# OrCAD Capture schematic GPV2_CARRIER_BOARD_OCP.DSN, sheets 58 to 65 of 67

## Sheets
58 064 P1V8: size C
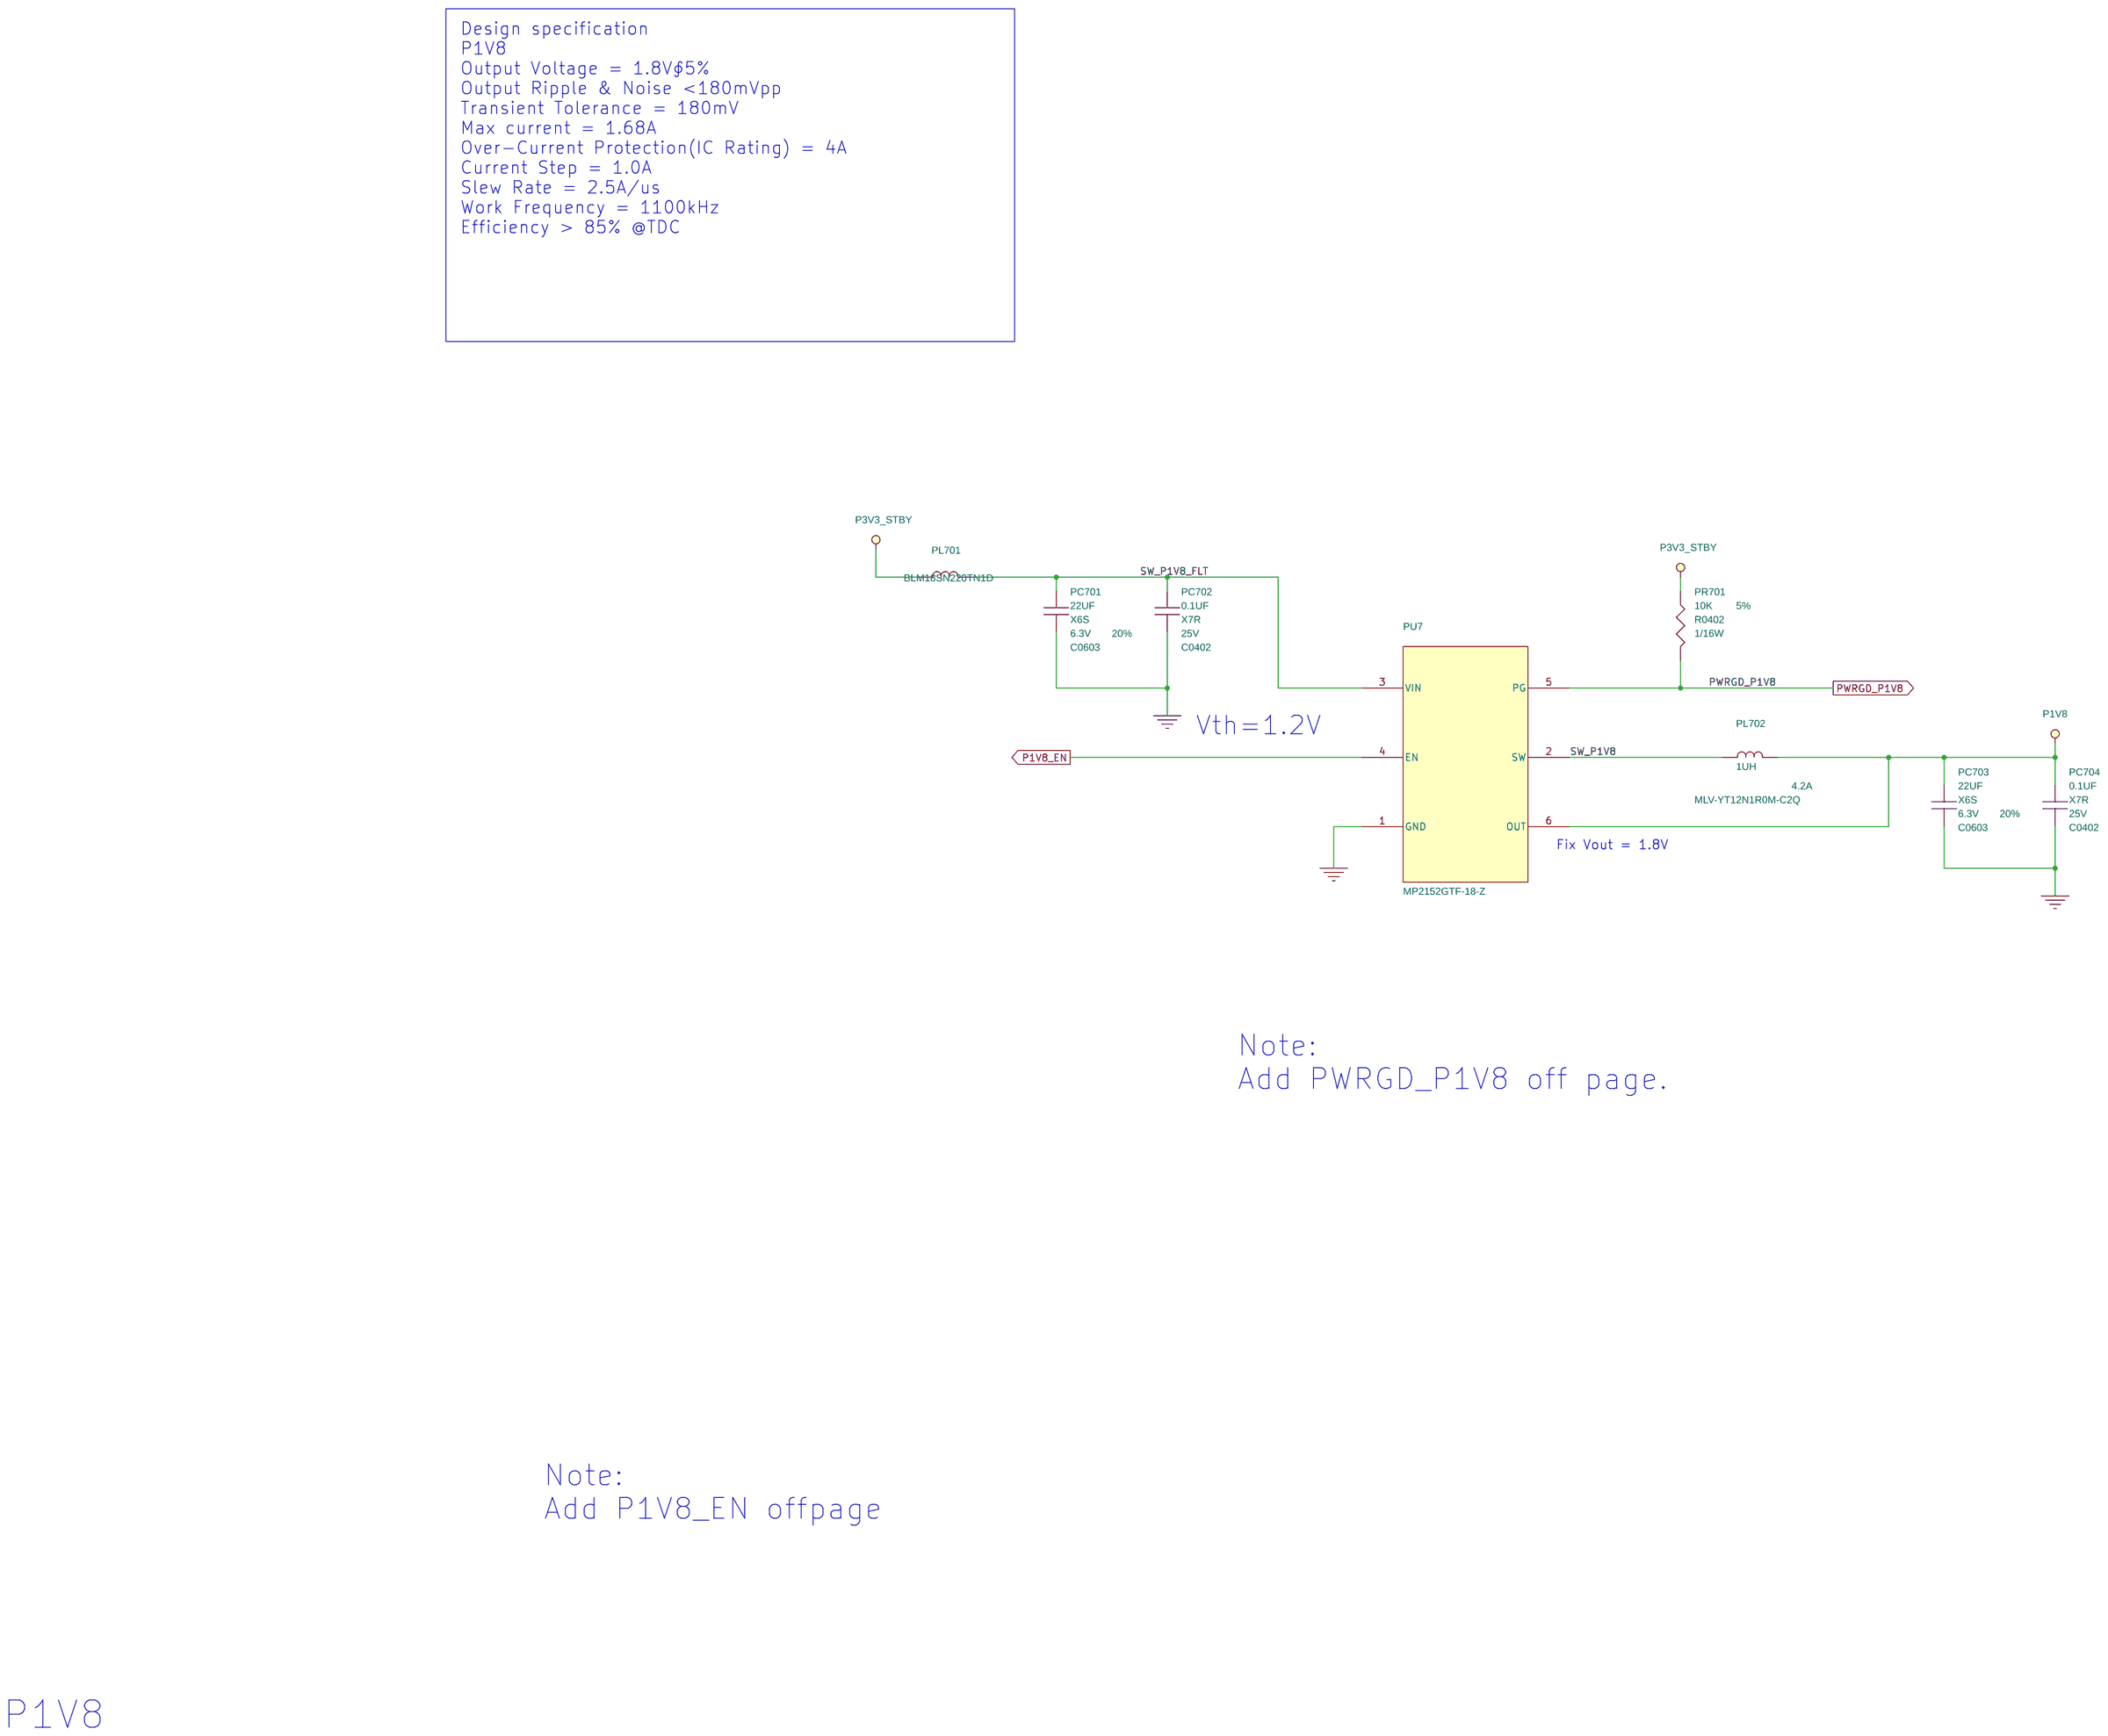
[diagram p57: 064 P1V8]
59 066 TDR: size C
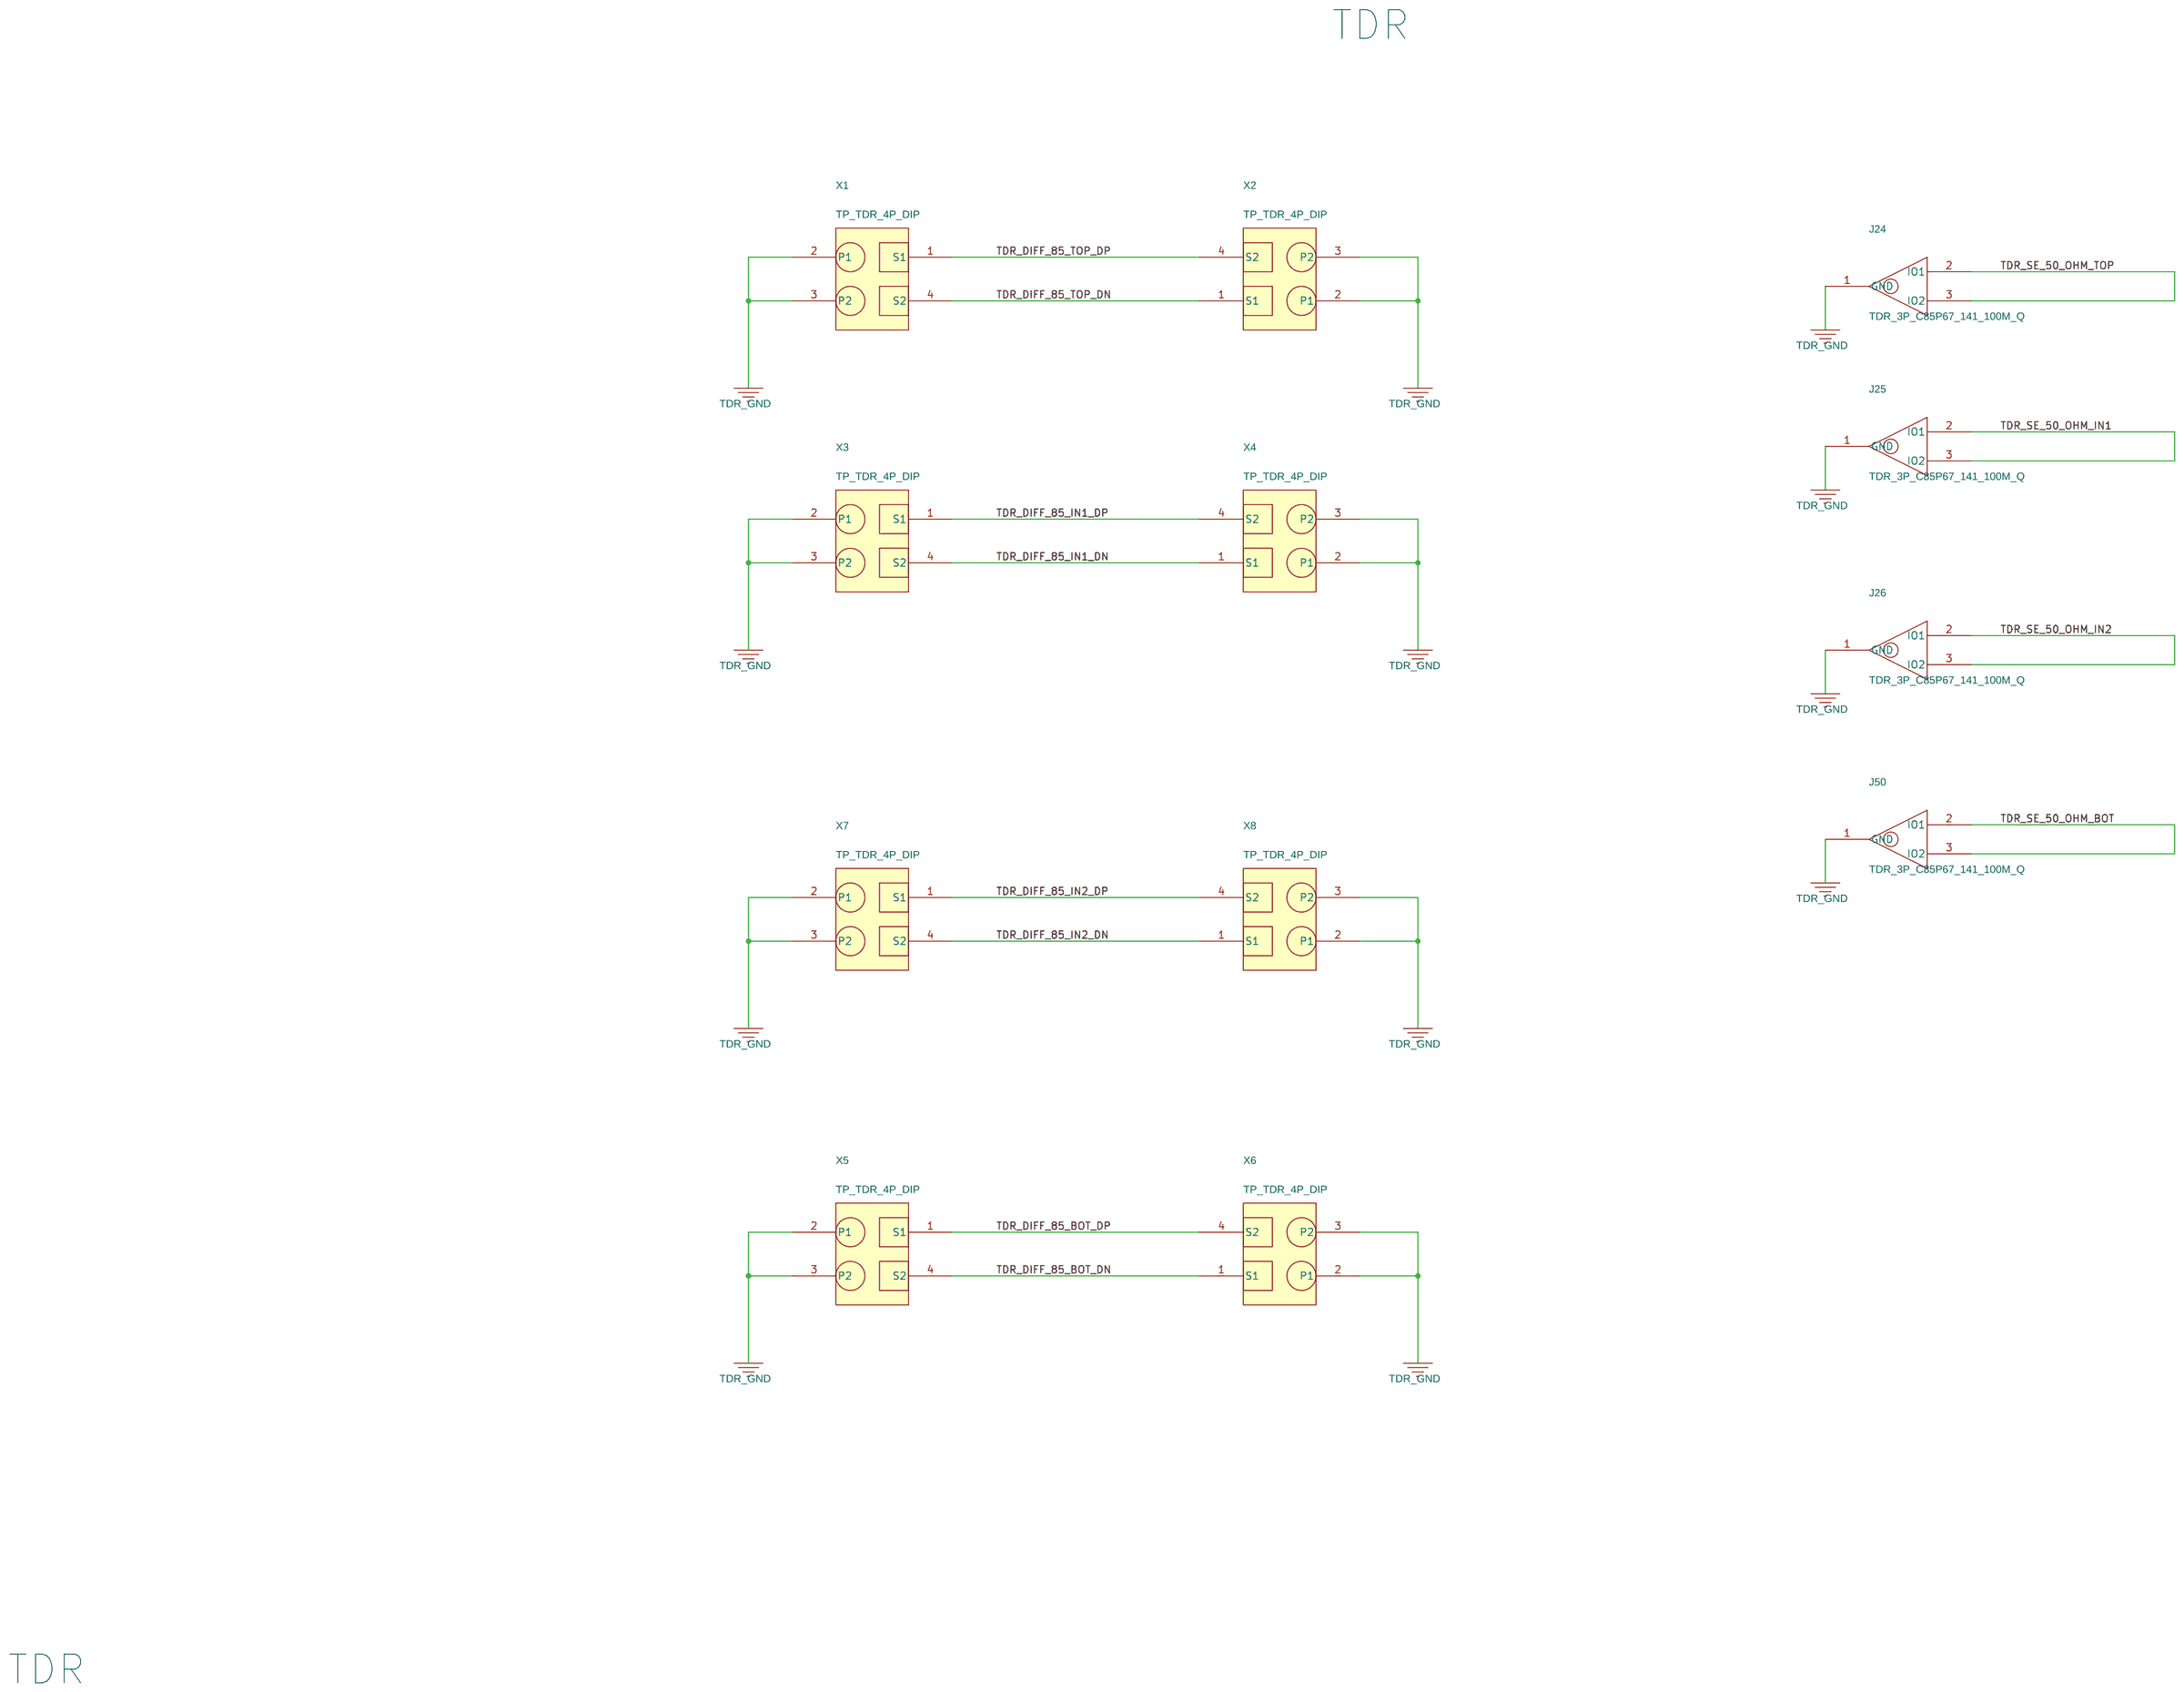
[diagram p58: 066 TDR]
60 067 DUMMY SYMBOL: size C
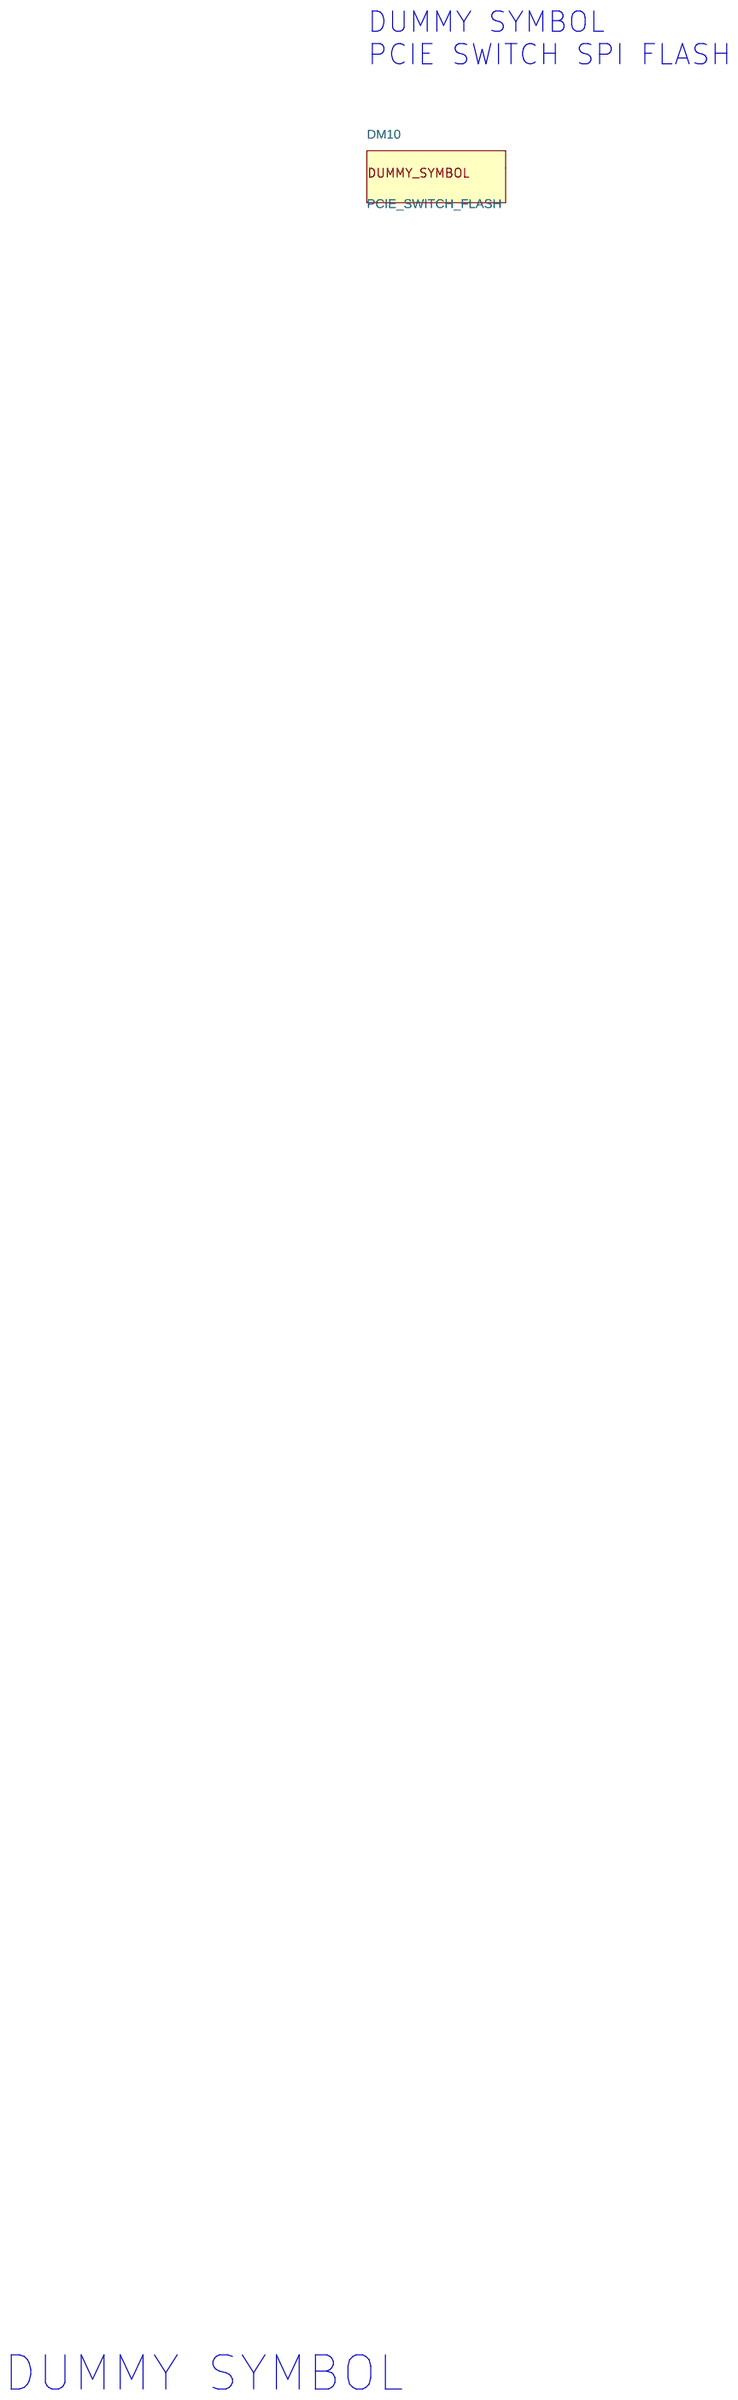
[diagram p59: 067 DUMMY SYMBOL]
61 041 INA230 / I2C MUX 7: size C
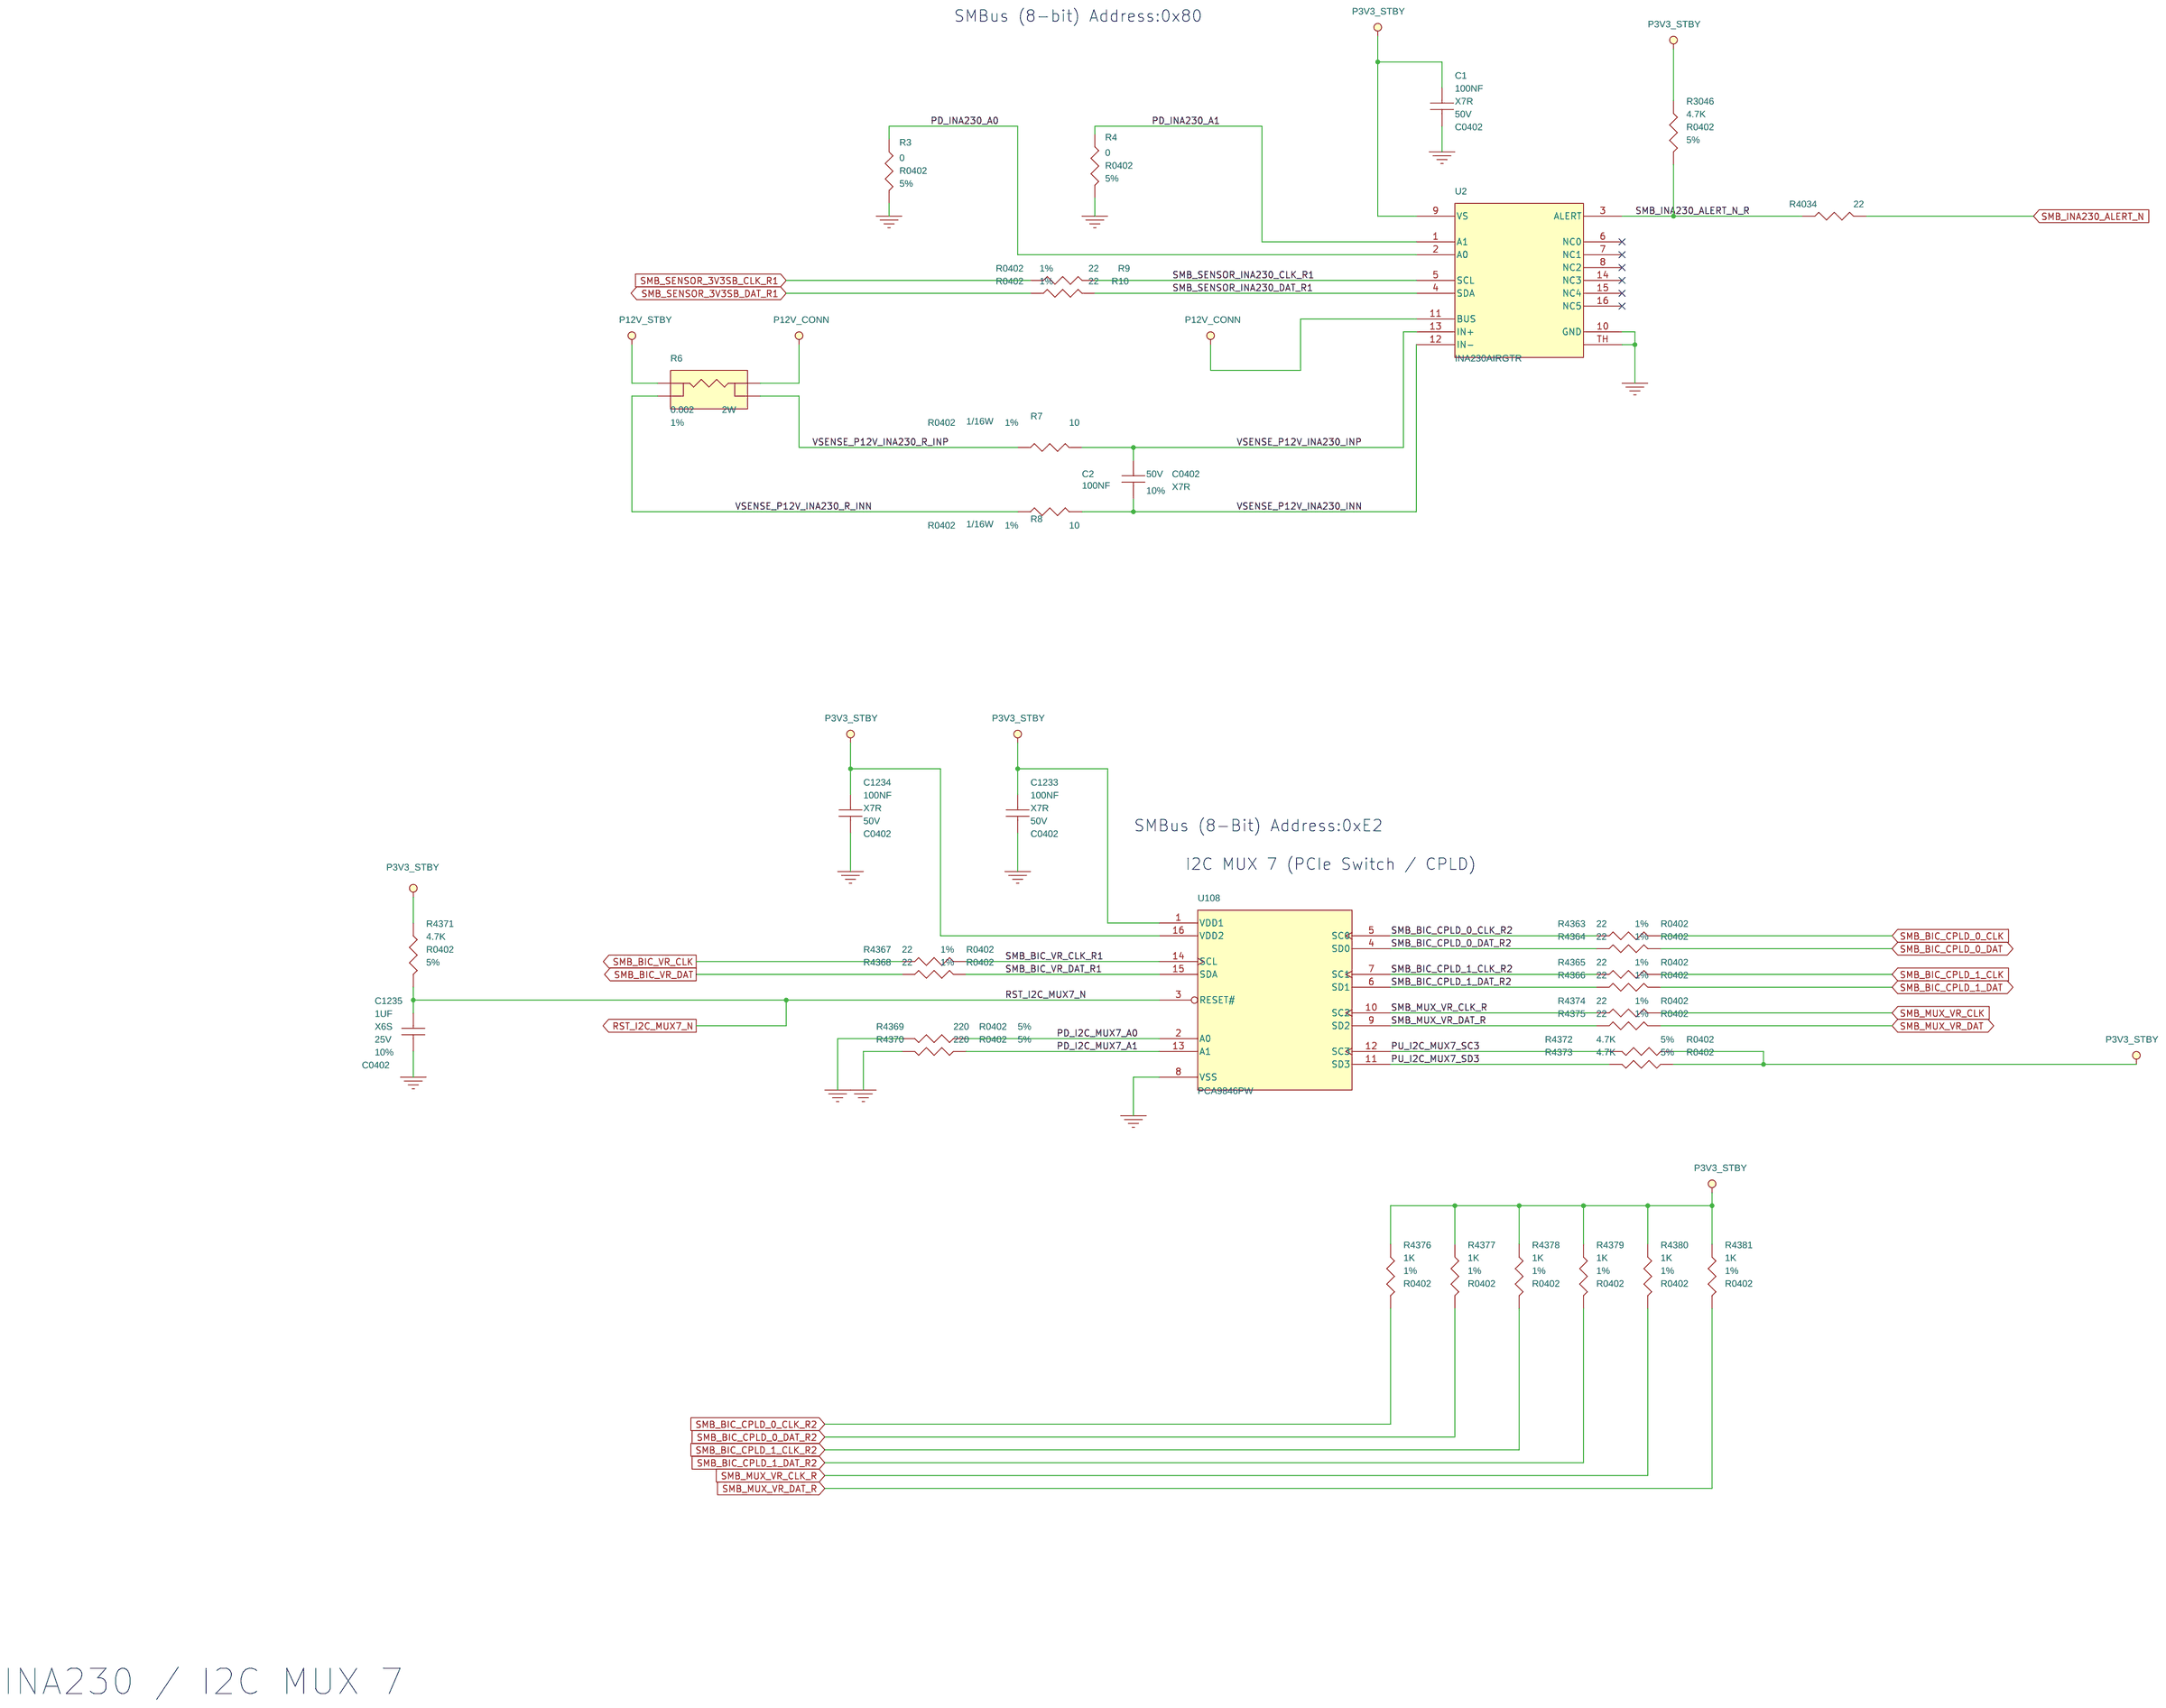
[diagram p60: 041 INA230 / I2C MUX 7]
62 022 SPI FLASH/EEPROM/JTAG: size C
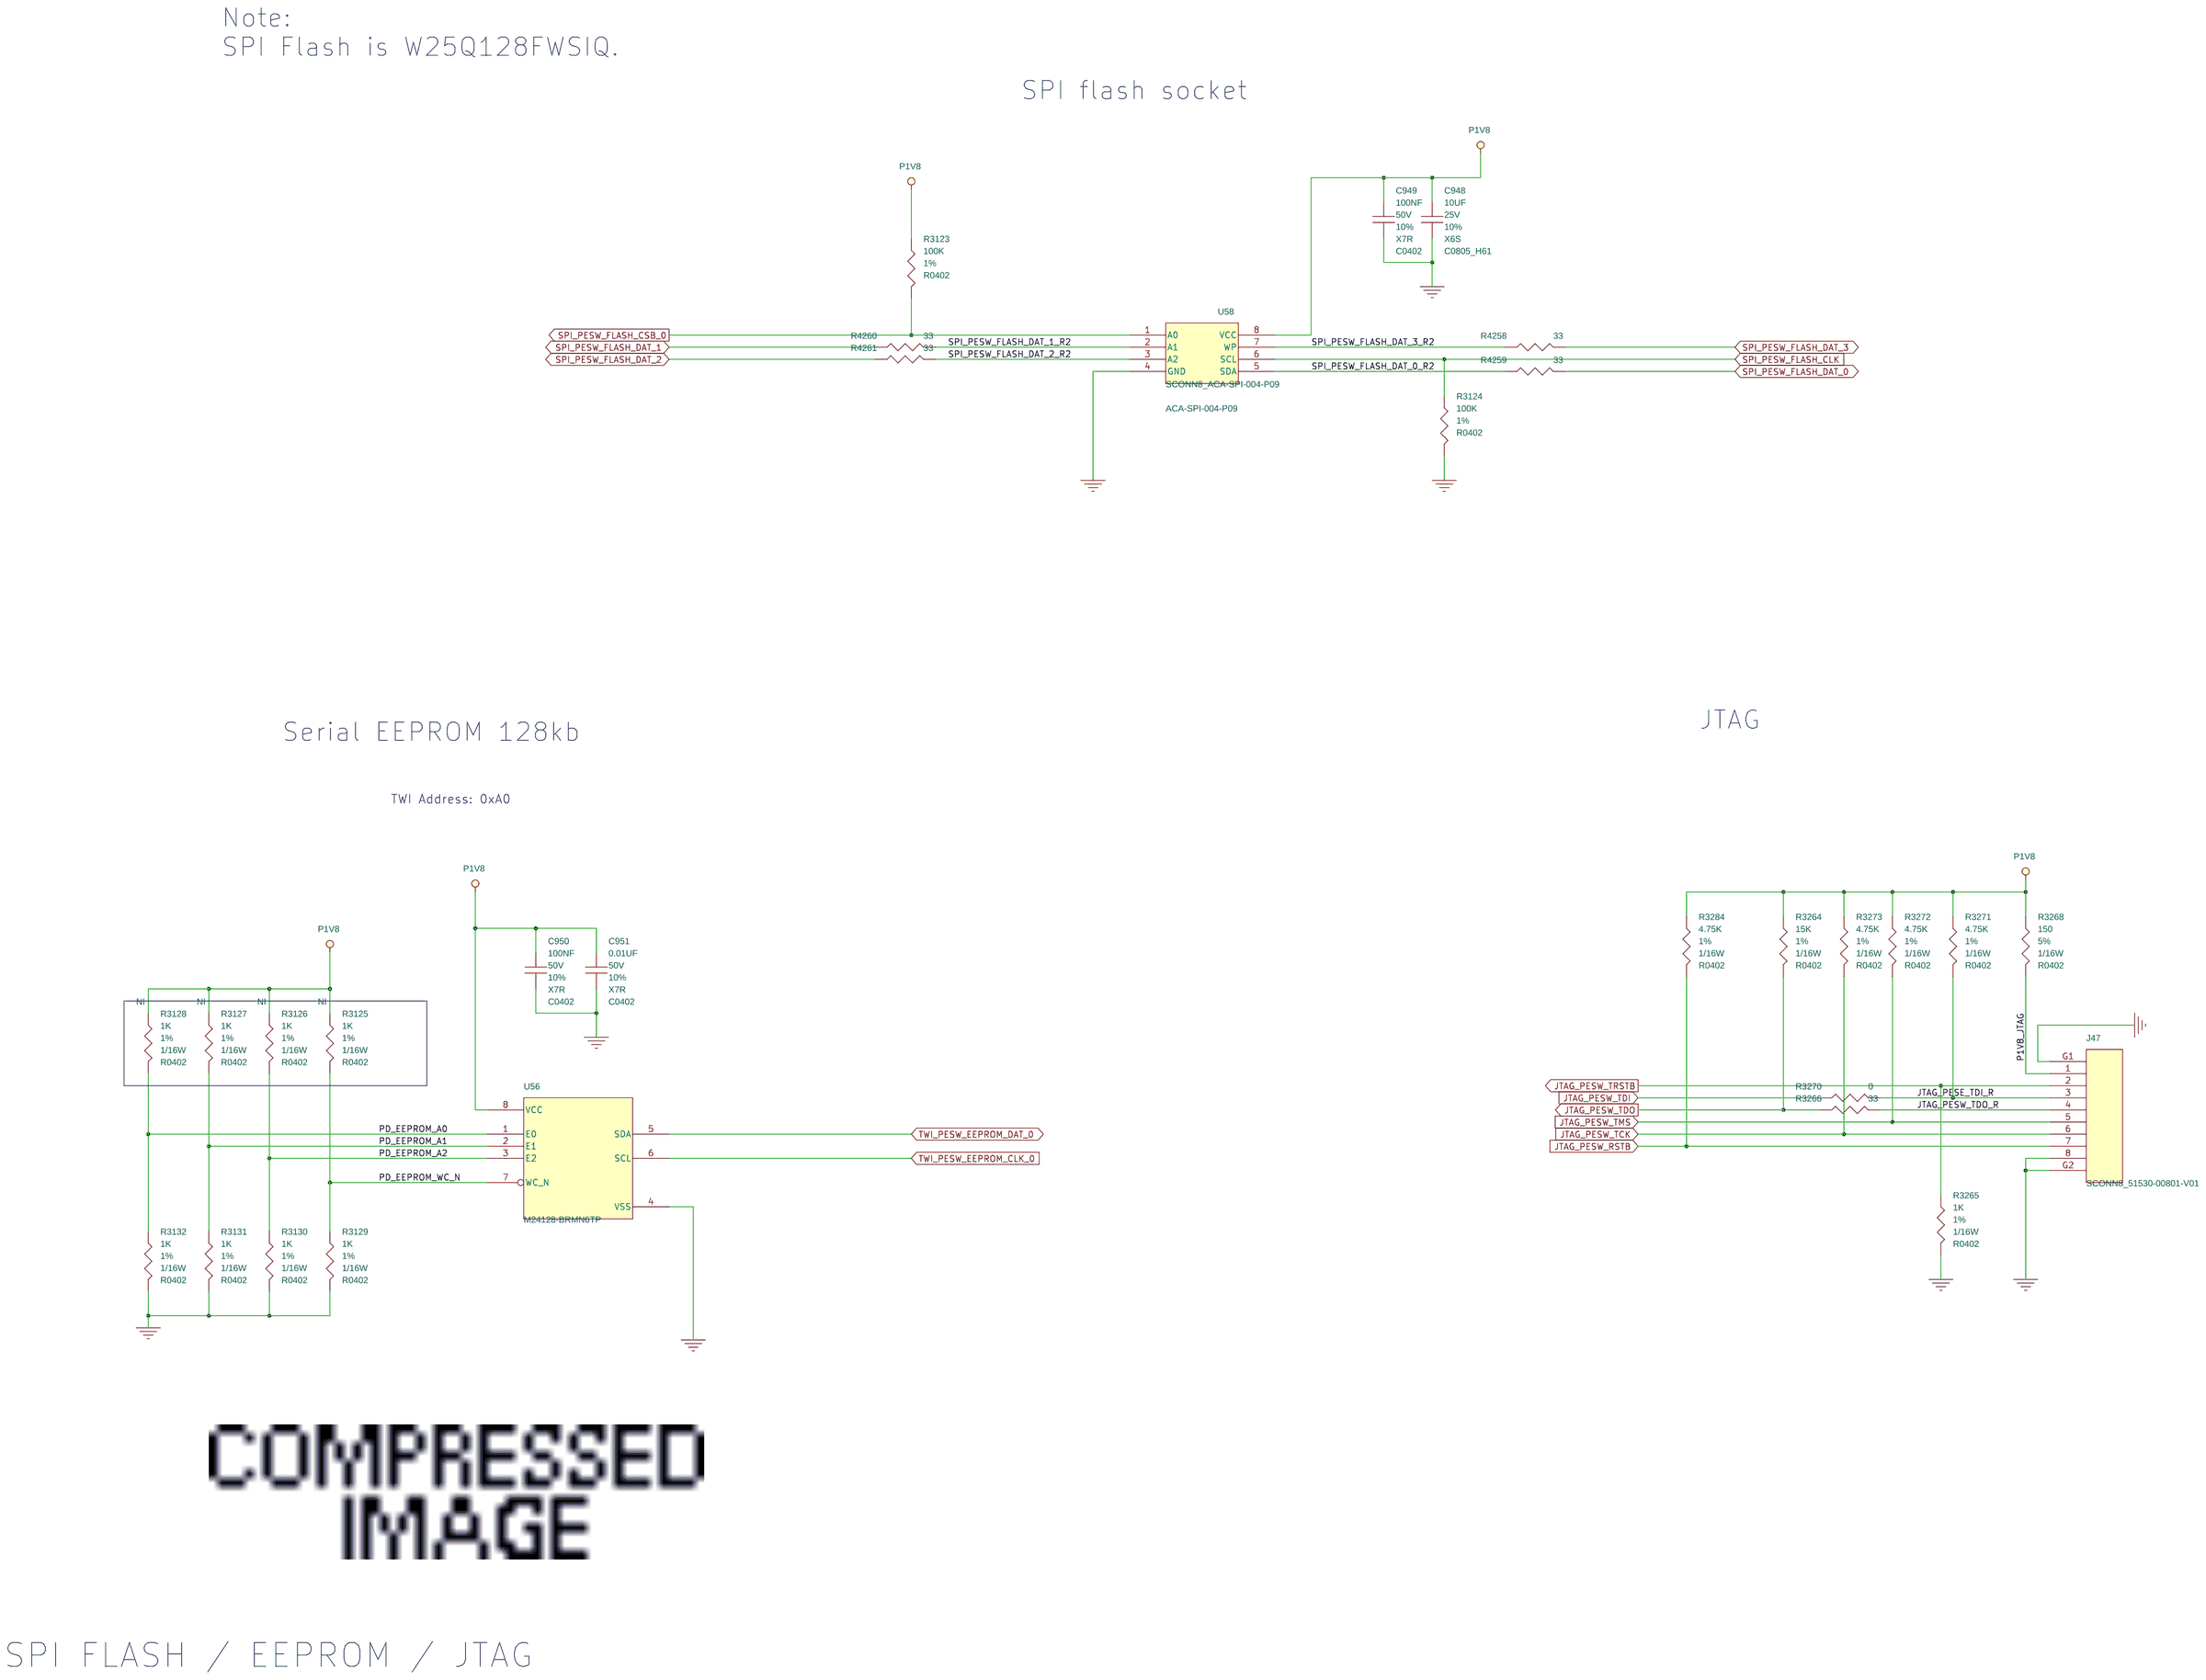
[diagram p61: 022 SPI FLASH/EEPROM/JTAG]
63 065 Mechanical/Delta-L: size C
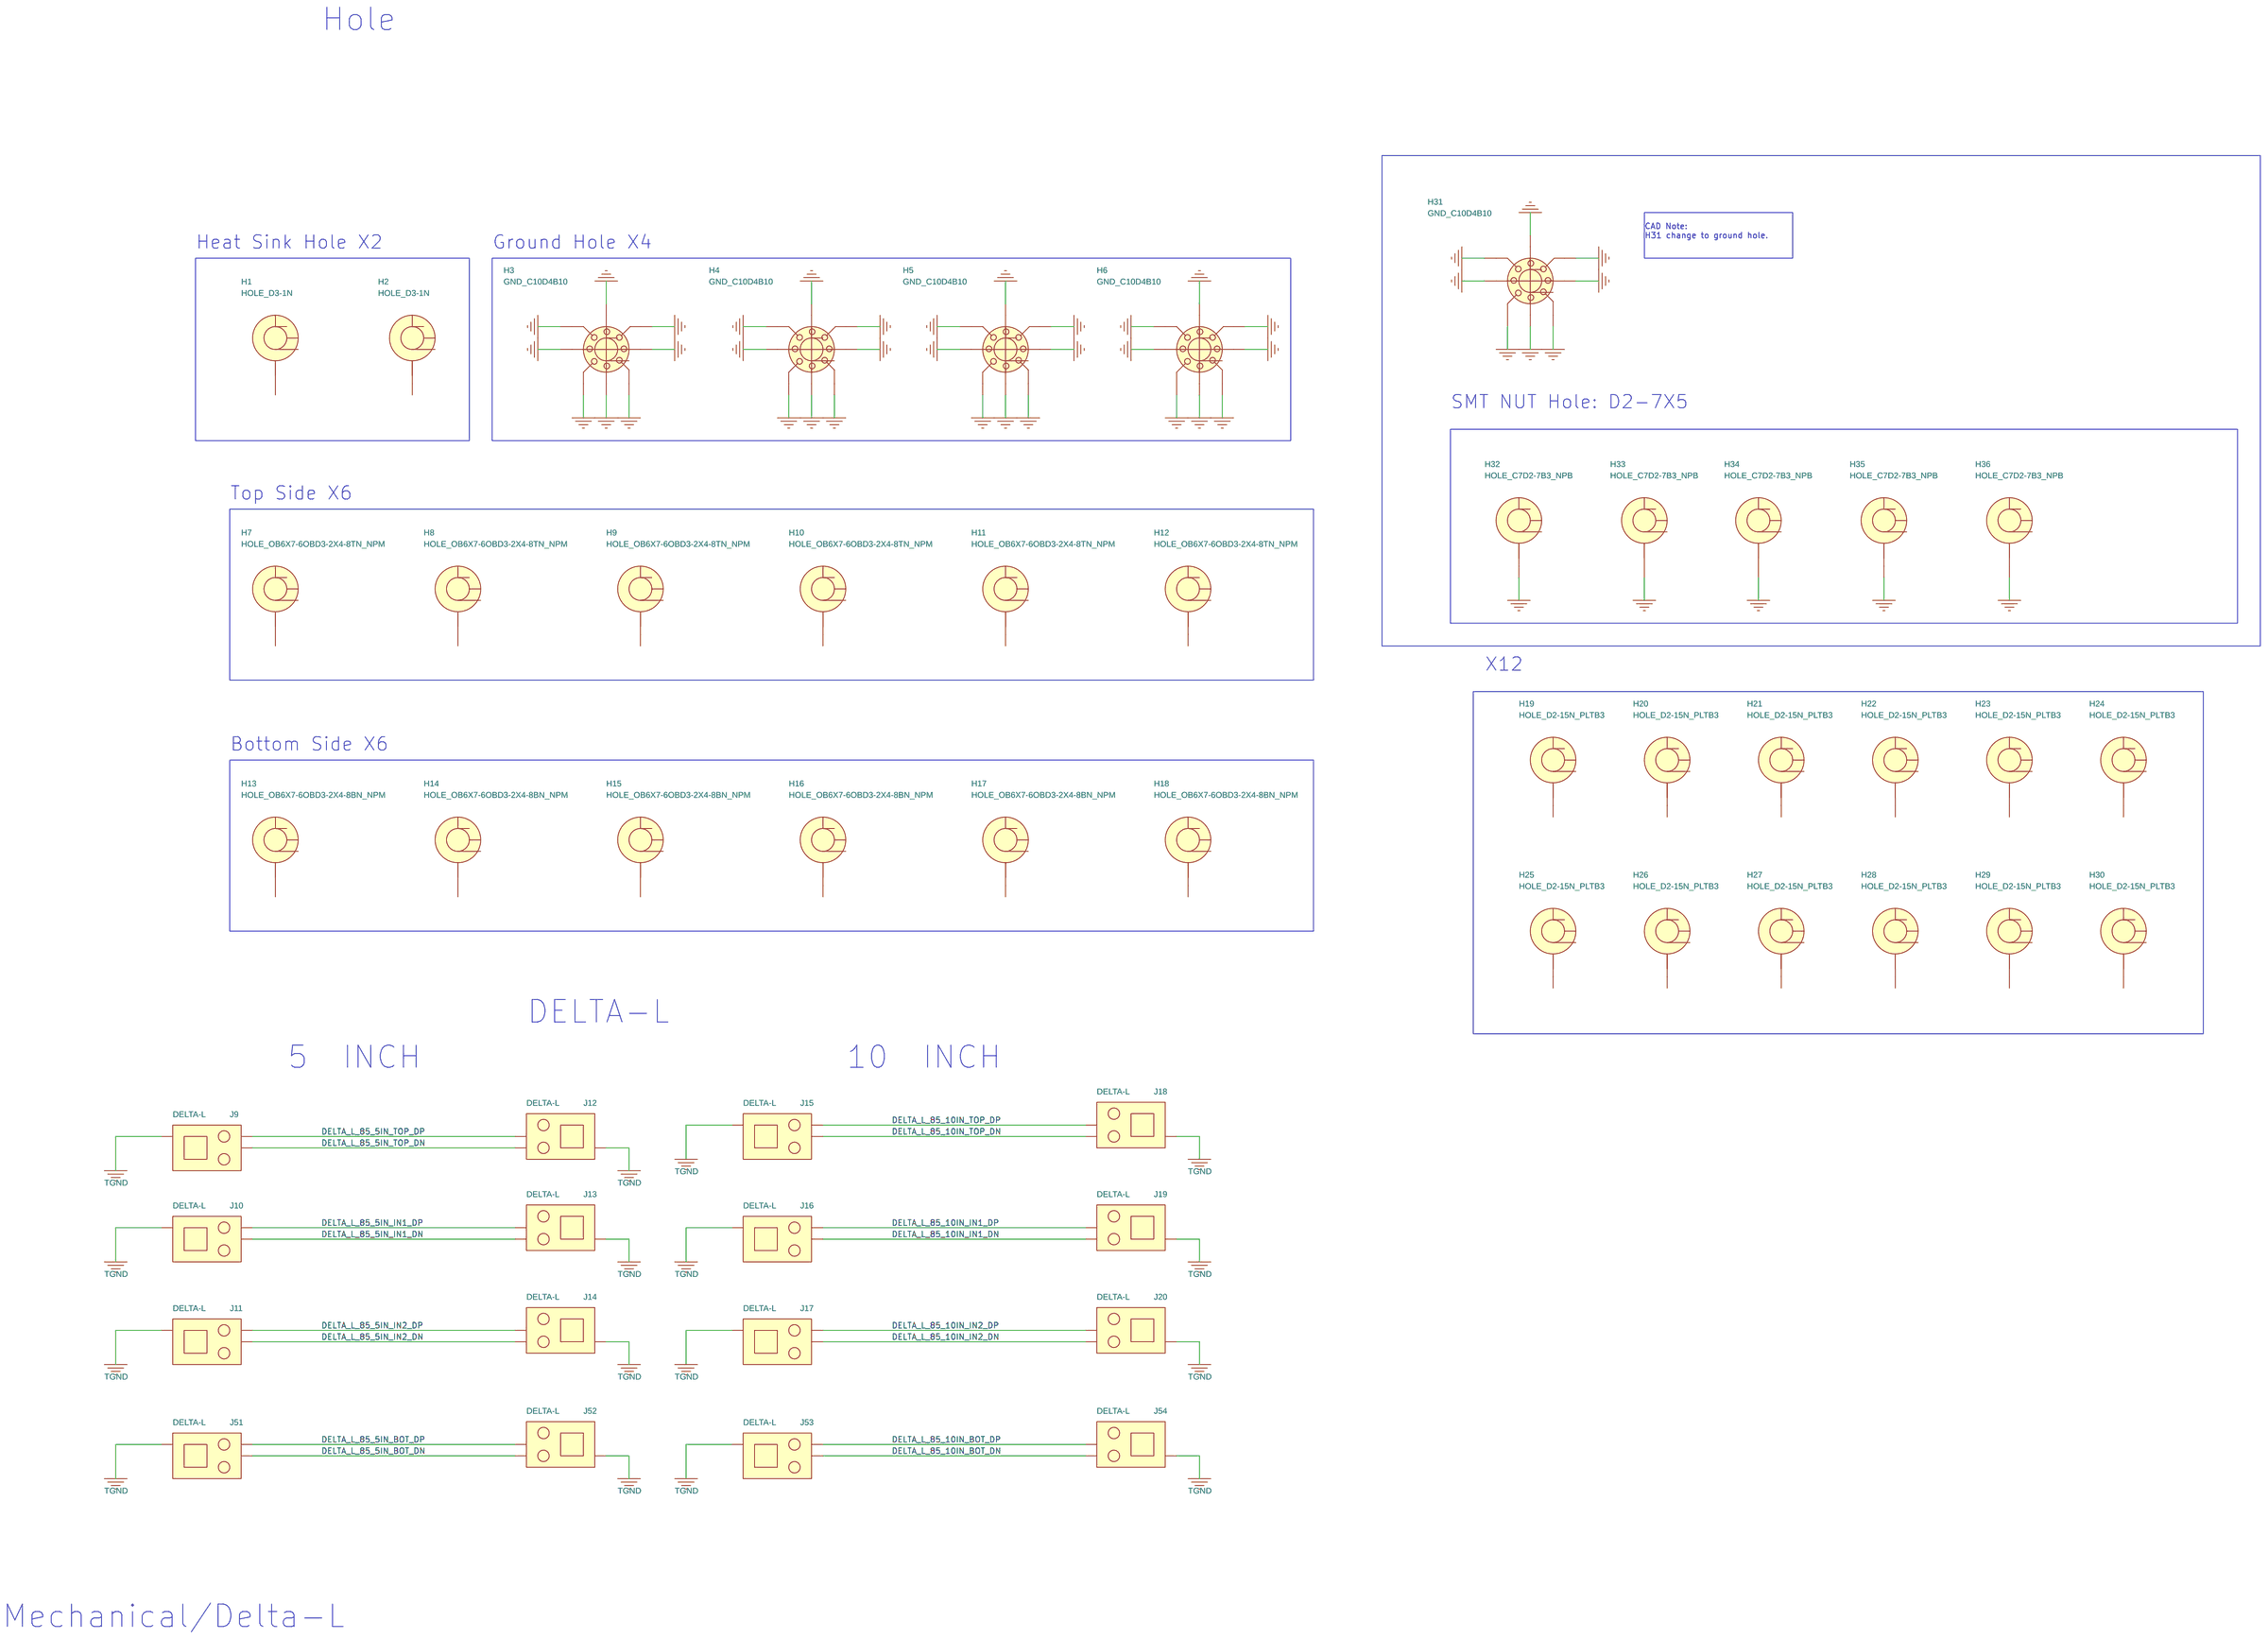
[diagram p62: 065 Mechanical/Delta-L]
64 020 PCIE SWITCH (PWR2/VSS2): size C
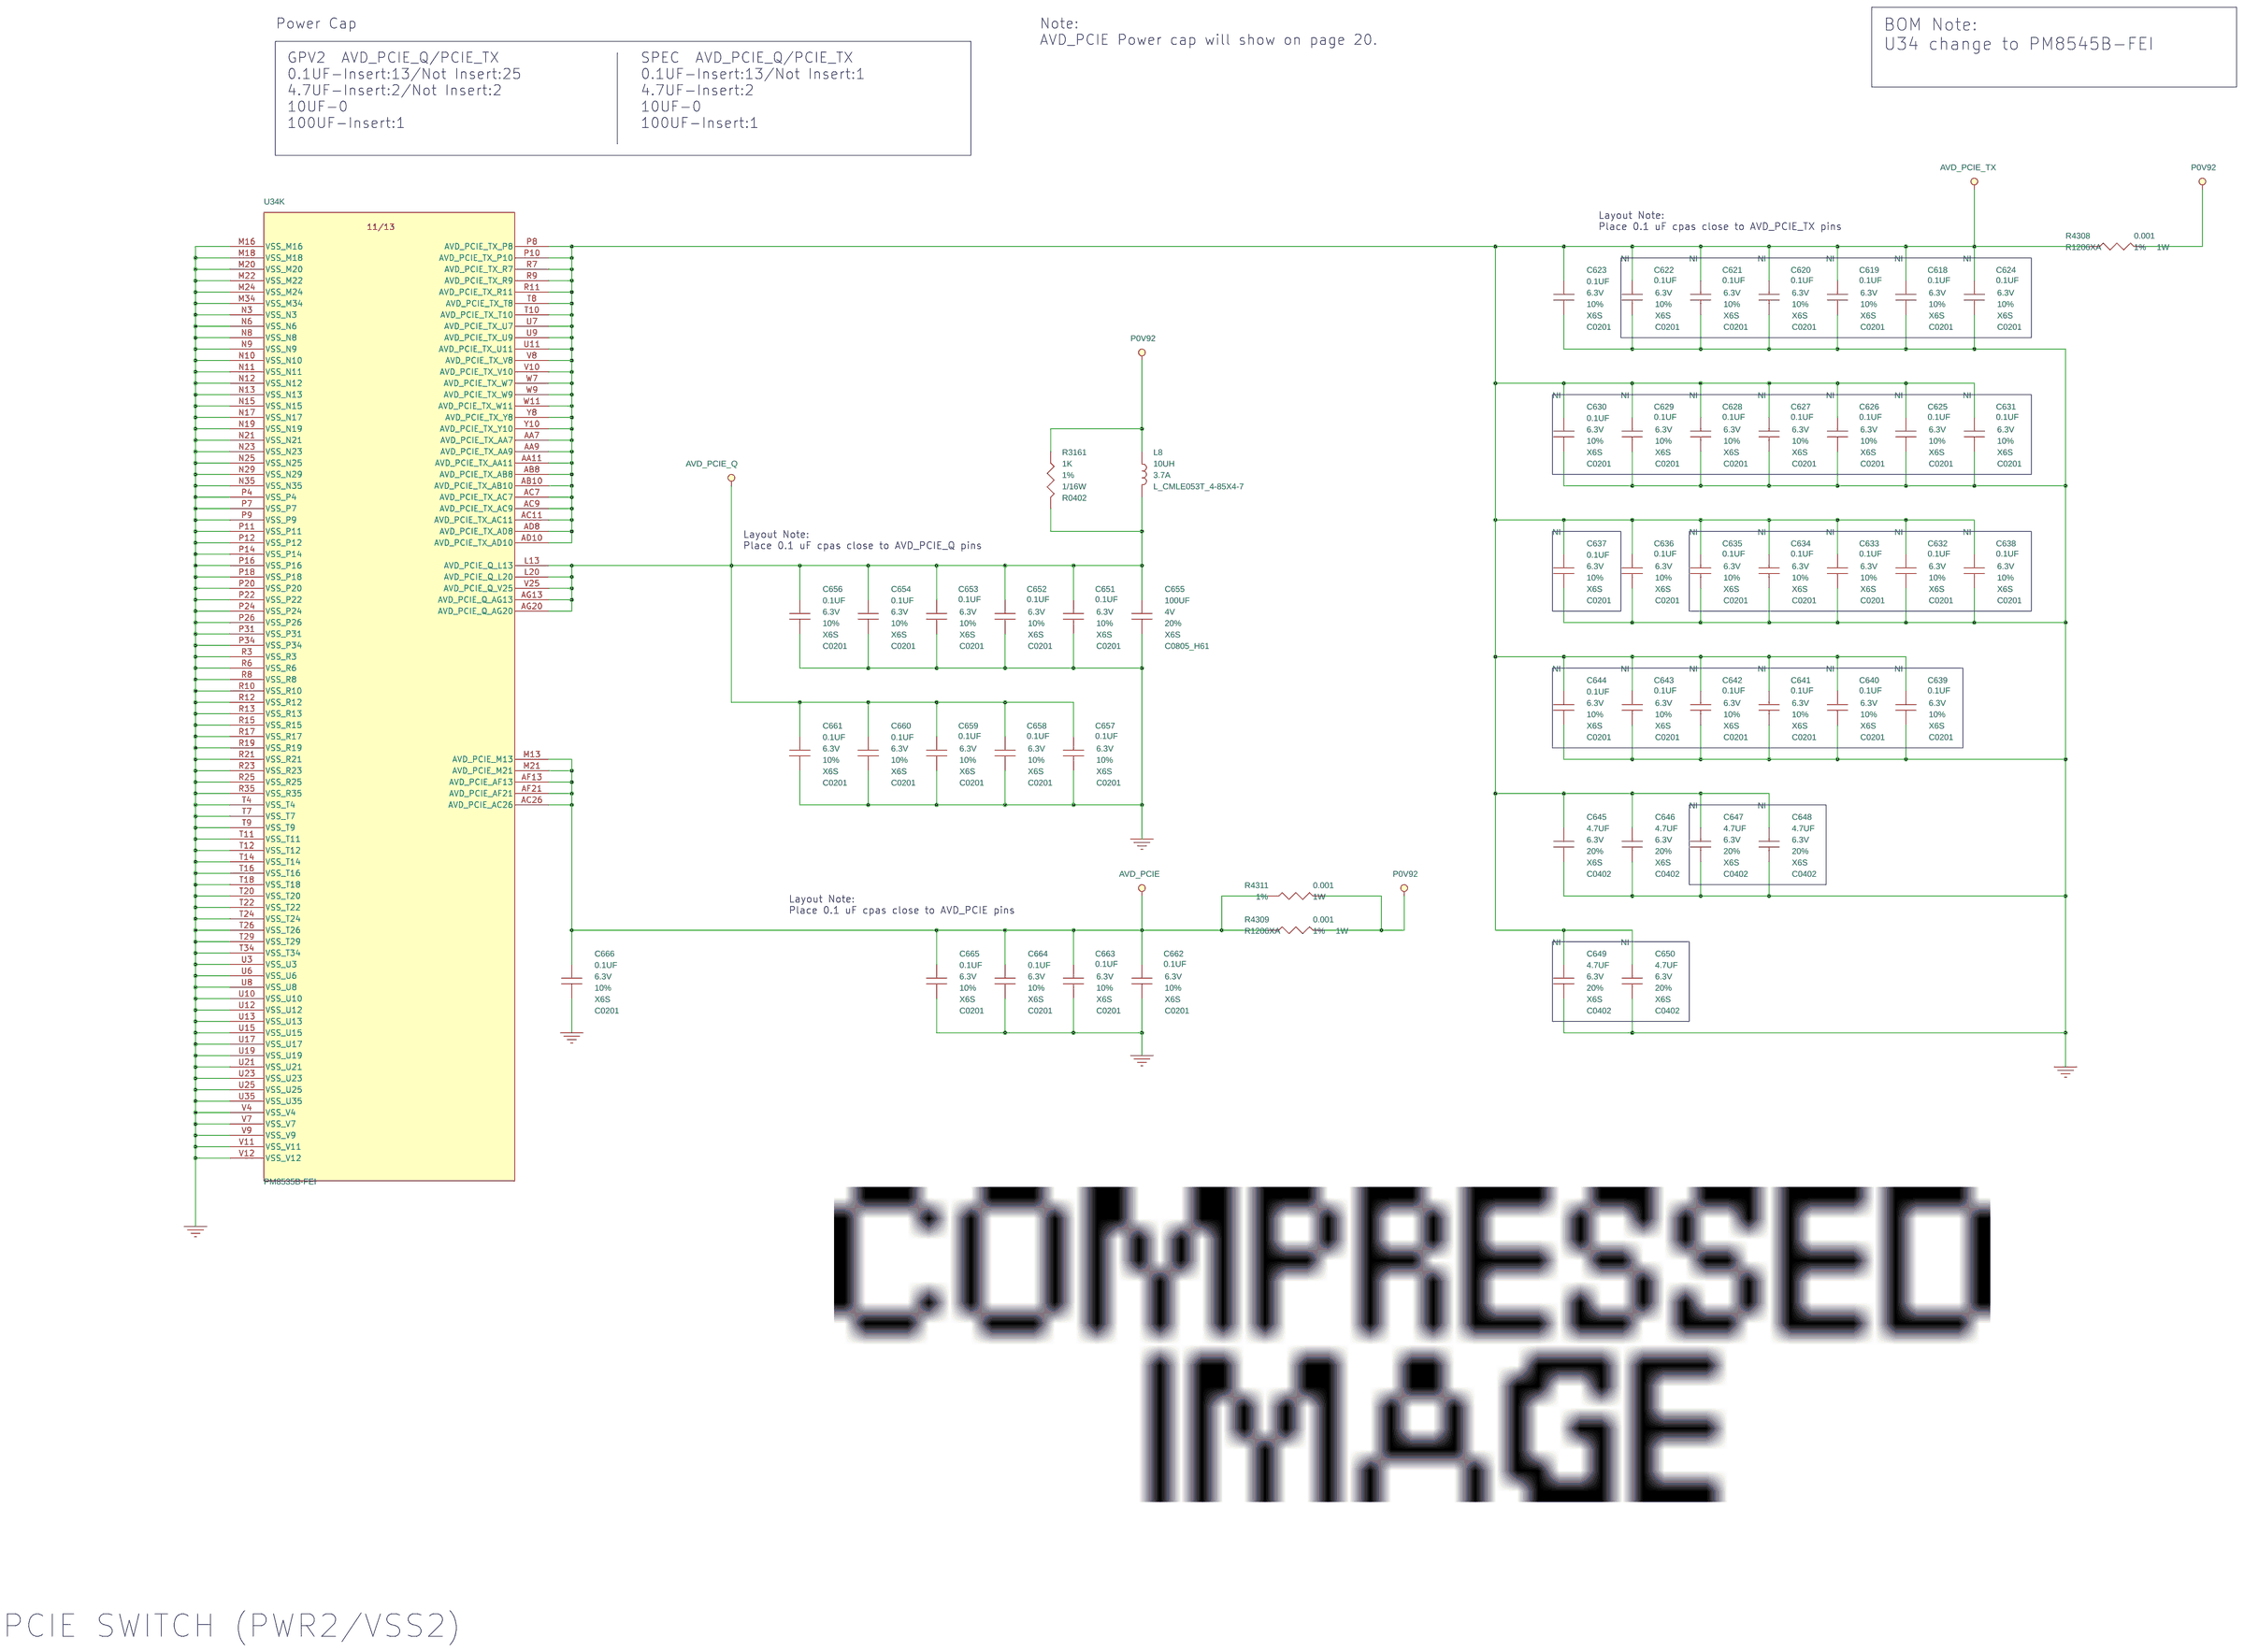
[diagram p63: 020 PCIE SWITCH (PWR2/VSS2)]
65 019 PCIE SWITCH (PWR1/VSS1): size C
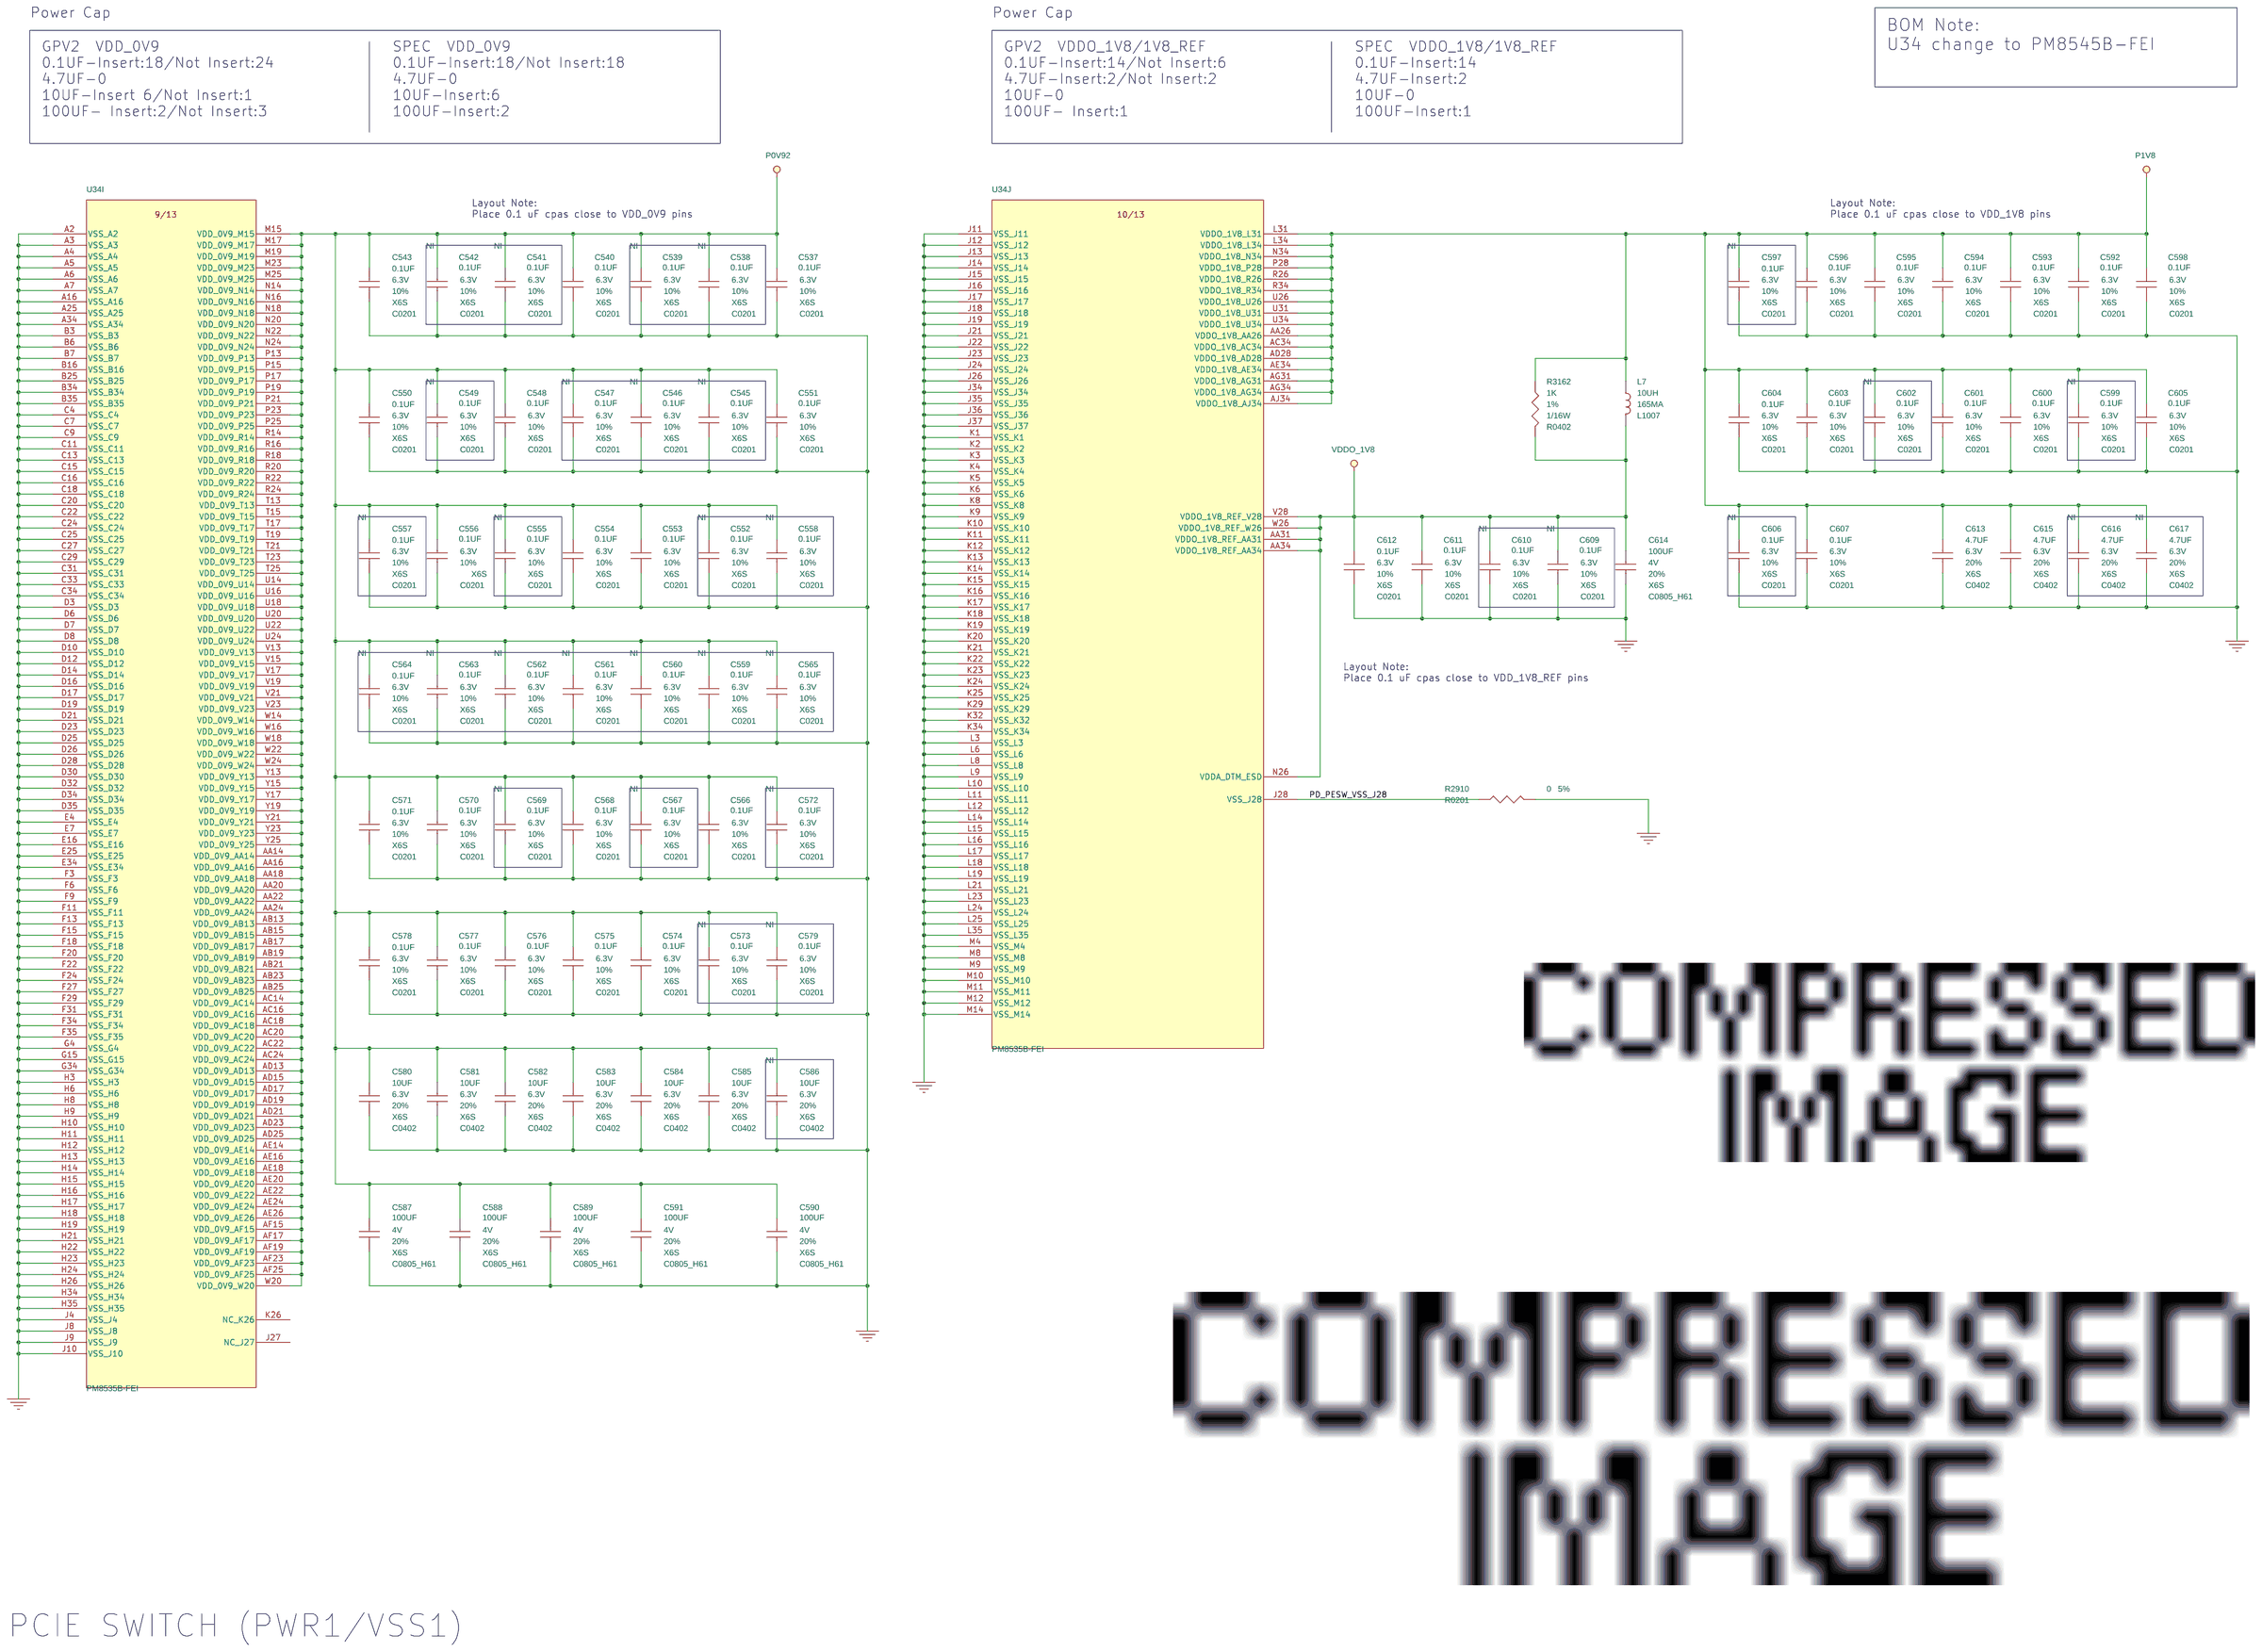
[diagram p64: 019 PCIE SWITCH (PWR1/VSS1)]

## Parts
sheet 017 PCIE SWITCH (CLOCKS/RESET)
U34  PM8535B-FEI  [BGA1311_1_37-5X37-5]  (sections A,B,C,D,E,F,G,H,I,J,K,L,M)
sheet 019 PCIE SWITCH (PWR1/VSS1)
C537  0.1UF  [C0201]
C538  0.1UF  [C0201]
C539  0.1UF  [C0201]
C540  0.1UF  [C0201]
C541  0.1UF  [C0201]
C542  0.1UF  [C0201]
C543  0.1UF  [C0201]
C545  0.1UF  [C0201]
C546  0.1UF  [C0201]
C547  0.1UF  [C0201]
C548  0.1UF  [C0201]
C549  0.1UF  [C0201]
C550  0.1UF  [C0201]
C551  0.1UF  [C0201]
C552  0.1UF  [C0201]
C553  0.1UF  [C0201]
C554  0.1UF  [C0201]
C555  0.1UF  [C0201]
C556  0.1UF  [C0201]
C557  0.1UF  [C0201]
C558  0.1UF  [C0201]
C559  0.1UF  [C0201]
C560  0.1UF  [C0201]
C561  0.1UF  [C0201]
C562  0.1UF  [C0201]
C563  0.1UF  [C0201]
C564  0.1UF  [C0201]
C565  0.1UF  [C0201]
C566  0.1UF  [C0201]
C567  0.1UF  [C0201]
C568  0.1UF  [C0201]
C569  0.1UF  [C0201]
C570  0.1UF  [C0201]
C571  0.1UF  [C0201]
C572  0.1UF  [C0201]
C573  0.1UF  [C0201]
C574  0.1UF  [C0201]
C575  0.1UF  [C0201]
C576  0.1UF  [C0201]
C577  0.1UF  [C0201]
C578  0.1UF  [C0201]
C579  0.1UF  [C0201]
C580  10UF  [C0402]
C581  10UF  [C0402]
C582  10UF  [C0402]
C583  10UF  [C0402]
C584  10UF  [C0402]
C585  10UF  [C0402]
C586  10UF  [C0402]
C587  100UF  [C0805_H61]
C588  100UF  [C0805_H61]
C589  100UF  [C0805_H61]
C590  100UF  [C0805_H61]
C591  100UF  [C0805_H61]
C592  0.1UF  [C0201]
C593  0.1UF  [C0201]
C594  0.1UF  [C0201]
C595  0.1UF  [C0201]
C596  0.1UF  [C0201]
C597  0.1UF  [C0201]
C598  0.1UF  [C0201]
C599  0.1UF  [C0201]
C600  0.1UF  [C0201]
C601  0.1UF  [C0201]
C602  0.1UF  [C0201]
C603  0.1UF  [C0201]
C604  0.1UF  [C0201]
C605  0.1UF  [C0201]
C606  0.1UF  [C0201]
C607  0.1UF  [C0201]
C609  0.1UF  [C0201]
C610  0.1UF  [C0201]
C611  0.1UF  [C0201]
C612  0.1UF  [C0201]
C613  4.7UF  [C0402]
C614  100UF  [C0805_H61]
C615  4.7UF  [C0402]
C616  4.7UF  [C0402]
C617  4.7UF  [C0402]
L7  10UH  [L1007]
R2910  0  [R0201]
R3162  1K  [R0402]
sheet 020 PCIE SWITCH (PWR2/VSS2)
C618  0.1UF  [C0201]
C619  0.1UF  [C0201]
C620  0.1UF  [C0201]
C621  0.1UF  [C0201]
C622  0.1UF  [C0201]
C623  0.1UF  [C0201]
C624  0.1UF  [C0201]
C625  0.1UF  [C0201]
C626  0.1UF  [C0201]
C627  0.1UF  [C0201]
C628  0.1UF  [C0201]
C629  0.1UF  [C0201]
C630  0.1UF  [C0201]
C631  0.1UF  [C0201]
C632  0.1UF  [C0201]
C633  0.1UF  [C0201]
C634  0.1UF  [C0201]
C635  0.1UF  [C0201]
C636  0.1UF  [C0201]
C637  0.1UF  [C0201]
C638  0.1UF  [C0201]
C639  0.1UF  [C0201]
C640  0.1UF  [C0201]
C641  0.1UF  [C0201]
C642  0.1UF  [C0201]
C643  0.1UF  [C0201]
C644  0.1UF  [C0201]
C645  4.7UF  [C0402]
C646  4.7UF  [C0402]
C647  4.7UF  [C0402]
C648  4.7UF  [C0402]
C649  4.7UF  [C0402]
C650  4.7UF  [C0402]
C651  0.1UF  [C0201]
C652  0.1UF  [C0201]
C653  0.1UF  [C0201]
C654  0.1UF  [C0201]
C655  100UF  [C0805_H61]
C656  0.1UF  [C0201]
C657  0.1UF  [C0201]
C658  0.1UF  [C0201]
C659  0.1UF  [C0201]
C660  0.1UF  [C0201]
C661  0.1UF  [C0201]
C662  0.1UF  [C0201]
C663  0.1UF  [C0201]
C664  0.1UF  [C0201]
C665  0.1UF  [C0201]
C666  0.1UF  [C0201]
L8  10UH  [L_CMLE053T_4-85X4-7]
R3161  1K  [R0402]
R4308  0.001  [R1206XA]
R4309  0.001  [R1206XA]
R4311  0.001  [R1206XA]
sheet 022 SPI FLASH/EEPROM/JTAG
C948  10UF  [C0805_H61]
C949  100NF  [C0402]
C950  100NF  [C0402]
C951  0.01UF  [C0402]
J47  SCONN8_51530-00801-V01  [CON_8S1H2S_P0-5XC]
R3123  100K  [R0402]
R3124  100K  [R0402]
R3125  1K  [R0402]
R3126  1K  [R0402]
R3127  1K  [R0402]
R3128  1K  [R0402]
R3129  1K  [R0402]
R3130  1K  [R0402]
R3131  1K  [R0402]
R3132  1K  [R0402]
R3264  15K  [R0402]
R3265  1K  [R0402]
R3266  33  [R0402]
R3268  150  [R0402]
R3270  0  [R0402]
R3271  4.75K  [R0402]
R3272  4.75K  [R0402]
R3273  4.75K  [R0402]
R3284  4.75K  [R0402]
R4258  33  [R0402]
R4259  33  [R0402]
R4260  33  [R0402]
R4261  33  [R0402]
U56  M24128-BRMN6TP  [SO8_1-27_4-9X3-9XA]
U58  SCONN8_ACA-SPI-004-P09  [SOCKET8SXD]
sheet 041 INA230 / I2C MUX 7
C1  100NF  [C0402]
C2  100NF  [C0402]
C1233  100NF  [C0402]
C1234  100NF  [C0402]
C1235  1UF  [C0402]
R3  0  [R0402]
R4  0  [R0402]
R6  0.002  [R2512_4PXF]
R7  10  [R0402]
R8  10  [R0402]
R9  22  [R0402]
R10  22  [R0402]
R3046  4.7K  [R0402]
R4034  22  [R0402]
R4363  22  [R0402]
R4364  22  [R0402]
R4365  22  [R0402]
R4366  22  [R0402]
R4367  22  [R0402]
R4368  22  [R0402]
R4369  220  [R0402]
R4370  220  [R0402]
R4371  4.7K  [R0402]
R4372  4.7K  [R0402]
R4373  4.7K  [R0402]
R4374  22  [R0402]
R4375  22  [R0402]
R4376  1K  [R0402]
R4377  1K  [R0402]
R4378  1K  [R0402]
R4379  1K  [R0402]
R4380  1K  [R0402]
R4381  1K  [R0402]
U2  INA230AIRGTR  [QFN16_THXI]
U108  PCA9846PW  [TSSOP16XD]
sheet 064 P1V8
PC701  22UF  [C0603]
PC702  0.1UF  [C0402]
PC703  22UF  [C0603]
PC704  0.1UF  [C0402]
PL701  BLM18SN220TN1D  [L0603]
PL702  1UH  [L_MLV-YT12N_2-5X2]
PR701  10K  [R0402]
PU7  MP2152GTF-18-Z  [SOT563-6_0-5_1-6X1-2XB]
sheet 065 Mechanical/Delta-L
H1  HOLE_D3-1N  [HOLE_D3-1N]
H2  HOLE_D3-1N  [HOLE_D3-1N]
H3  GNDHOLE_8PIN  [GND_C10D4B10]
H4  GNDHOLE_8PIN  [GND_C10D4B10]
H5  GNDHOLE_8PIN  [GND_C10D4B10]
H6  GNDHOLE_8PIN  [GND_C10D4B10]
H7  HOLE_OB6X7-6OBD3-2X4-8TN_NPM  [HOLE_OB6X7-6OBD3-2X4-8TN_NPM]
H8  HOLE_OB6X7-6OBD3-2X4-8TN_NPM  [HOLE_OB6X7-6OBD3-2X4-8TN_NPM]
H9  HOLE_OB6X7-6OBD3-2X4-8TN_NPM  [HOLE_OB6X7-6OBD3-2X4-8TN_NPM]
H10  HOLE_OB6X7-6OBD3-2X4-8TN_NPM  [HOLE_OB6X7-6OBD3-2X4-8TN_NPM]
H11  HOLE_OB6X7-6OBD3-2X4-8TN_NPM  [HOLE_OB6X7-6OBD3-2X4-8TN_NPM]
H12  HOLE_OB6X7-6OBD3-2X4-8TN_NPM  [HOLE_OB6X7-6OBD3-2X4-8TN_NPM]
H13  HOLE_OB6X7-6OBD3-2X4-8BN_NPM  [HOLE_OB6X7-6OBD3-2X4-8BN_NPM]
H14  HOLE_OB6X7-6OBD3-2X4-8BN_NPM  [HOLE_OB6X7-6OBD3-2X4-8BN_NPM]
H15  HOLE_OB6X7-6OBD3-2X4-8BN_NPM  [HOLE_OB6X7-6OBD3-2X4-8BN_NPM]
H16  HOLE_OB6X7-6OBD3-2X4-8BN_NPM  [HOLE_OB6X7-6OBD3-2X4-8BN_NPM]
H17  HOLE_OB6X7-6OBD3-2X4-8BN_NPM  [HOLE_OB6X7-6OBD3-2X4-8BN_NPM]
H18  HOLE_OB6X7-6OBD3-2X4-8BN_NPM  [HOLE_OB6X7-6OBD3-2X4-8BN_NPM]
H19  HOLE_D2-15N_PLTB3  [HOLE_D2-15N_PLTB3]
H20  HOLE_D2-15N_PLTB3  [HOLE_D2-15N_PLTB3]
H21  HOLE_D2-15N_PLTB3  [HOLE_D2-15N_PLTB3]
H22  HOLE_D2-15N_PLTB3  [HOLE_D2-15N_PLTB3]
H23  HOLE_D2-15N_PLTB3  [HOLE_D2-15N_PLTB3]
H24  HOLE_D2-15N_PLTB3  [HOLE_D2-15N_PLTB3]
H25  HOLE_D2-15N_PLTB3  [HOLE_D2-15N_PLTB3]
H26  HOLE_D2-15N_PLTB3  [HOLE_D2-15N_PLTB3]
H27  HOLE_D2-15N_PLTB3  [HOLE_D2-15N_PLTB3]
H28  HOLE_D2-15N_PLTB3  [HOLE_D2-15N_PLTB3]
H29  HOLE_D2-15N_PLTB3  [HOLE_D2-15N_PLTB3]
H30  HOLE_D2-15N_PLTB3  [HOLE_D2-15N_PLTB3]
H31  GNDHOLE_8PIN  [GND_C10D4B10]
H32  HOLE_C7D2-7B3_NPB  [HOLE_C7D2-7B3_NPB]
H33  HOLE_C7D2-7B3_NPB  [HOLE_C7D2-7B3_NPB]
H34  HOLE_C7D2-7B3_NPB  [HOLE_C7D2-7B3_NPB]
H35  HOLE_C7D2-7B3_NPB  [HOLE_C7D2-7B3_NPB]
H36  HOLE_C7D2-7B3_NPB  [HOLE_C7D2-7B3_NPB]
J9  DELTA-L  [TRIANG_LAUNCH_3PXA]
J10  DELTA-L  [TRIANG_LAUNCH_3PXA]
J11  DELTA-L  [TRIANG_LAUNCH_3PXA]
J12  DELTA-L  [TRIANG_LAUNCH_3PXA]
J13  DELTA-L  [TRIANG_LAUNCH_3PXA]
J14  DELTA-L  [TRIANG_LAUNCH_3PXA]
J15  DELTA-L  [TRIANG_LAUNCH_3PXA]
J16  DELTA-L  [TRIANG_LAUNCH_3PXA]
J17  DELTA-L  [TRIANG_LAUNCH_3PXA]
J18  DELTA-L  [TRIANG_LAUNCH_3PXA]
J19  DELTA-L  [TRIANG_LAUNCH_3PXA]
J20  DELTA-L  [TRIANG_LAUNCH_3PXA]
J51  DELTA-L  [TRIANG_LAUNCH_3PXA]
J52  DELTA-L  [TRIANG_LAUNCH_3PXA]
J53  DELTA-L  [TRIANG_LAUNCH_3PXA]
J54  DELTA-L  [TRIANG_LAUNCH_3PXA]
sheet 066 TDR
J24  TDR_3P_C85P67_141_100M_Q  [TDR_3P_C85P67_141_100M_Q]
J25  TDR_3P_C85P67_141_100M_Q  [TDR_3P_C85P67_141_100M_Q]
J26  TDR_3P_C85P67_141_100M_Q  [TDR_3P_C85P67_141_100M_Q]
J50  TDR_3P_C85P67_141_100M_Q  [TDR_3P_C85P67_141_100M_Q]
X1  TP_TDR_4P_DIP  [MPKT4_H025P0200]
X2  TP_TDR_4P_DIP  [MPKT4_H025P0200]
X3  TP_TDR_4P_DIP  [MPKT4_H025P0200]
X4  TP_TDR_4P_DIP  [MPKT4_H025P0200]
X5  TP_TDR_4P_DIP  [MPKT4_H025P0200]
X6  TP_TDR_4P_DIP  [MPKT4_H025P0200]
X7  TP_TDR_4P_DIP  [MPKT4_H025P0200]
X8  TP_TDR_4P_DIP  [MPKT4_H025P0200]
sheet 067 DUMMY SYMBOL
DM10  PCIE_SWITCH_FLASH  [TP30_FOR_BOM]

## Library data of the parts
U34 = PM8535BFEI: IC CTRL(1311P)PM8535B-FEI(FCBGA); CLASS: IC; ESD_CDM: N/A; ESD_HBM: N/A; ESD_MM: N/A; MATERIAL: IC; MSD: NA; Manuf_name: Microsemi Corporation ( Microsemi Taiwan); Manuftr: MST; PIN_LENGTH_LONG_PIN: 0 MILS; PIN_LENGTH_SHORT_PIN: 0 MILS; Part_Type: *LF_Chipset
C537 C540 C543 C548 C550 C551 C553 C554 C556 C566 C568 C570 C571 C574-C578 C592-C596 C598 C600 C601 C603-C605 C607 C611 C612 C623 C636 C651-C654 C656-C666 = CAP_NP: CAP CHIP 0.1UF 6.3V(10%,X6S,0201,H0.3); CLASS: DISCRETE; MATERIAL: X6S; Manuf_PN: GRM033C80J104K; Manuf_name: MURATA ERIE N.A. INC TAIWAN BRANCH Okayama Murata Mfg.Co.,Ltd.Wakura Murata Mfg.; Manuftr: MUR; Part_Type: *LF_C0201; TOLERANCE: 10%; VOLTAGE: 6.3V
C538 C539 C541 C542 C545-C547 C549 C552 C555 C557-C565 C567 C569 C572 C573 C579 C597 C599 C602 C606 C609 C610 C618-C622 C624-C635 C637-C644 = CAP_NP: CAP CHIP 0.1UF 6.3V(10%,X6S,0201,H0.3); CLASS: DISCRETE; MATERIAL: X6S; Manuf_PN: GRM033C80J104K; Manuf_name: MURATA ERIE N.A. INC TAIWAN BRANCH Okayama Murata Mfg.Co.,Ltd.Wakura Murata Mfg.; Manuftr: MUR; Not_insert: NI; Part_Type: *LF_C0201; TOLERANCE: 10%; VOLTAGE: 6.3V
C580-C585 = CAP_NP: CAP CHIP 10UF 6.3V(+-20%,X6S,0402); CLASS: DISCRETE; MATERIAL: X6S; Manuf_PN: GRM155C80J106M; Manuf_name: MURATA ERIE N.A. INC TAIWAN BRANCH Okayama Murata Mfg.Co.,; Manuftr: MUR; Part_Type: *LF_C0402; TOLERANCE: 20%; VOLTAGE: 6.3V
C586 = CAP_NP: CAP CHIP 10UF 6.3V(+-20%,X6S,0402); CLASS: DISCRETE; MATERIAL: X6S; Manuf_PN: GRM155C80J106M; Manuf_name: MURATA ERIE N.A. INC TAIWAN BRANCH Okayama Murata Mfg.Co.,; Manuftr: MUR; Not_insert: NI; Part_Type: *LF_C0402; TOLERANCE: 20%; VOLTAGE: 6.3V
C587-C591 C614 C655 = CAP_NP: CAP CHIP 100U 4V(+-20%,X6S,0805); CLASS: DISCRETE; MATERIAL: X6S; Manuf_PN: GRM21BC80G107M; Manuf_name: MURATA ERIE N.A. INC TAIWAN BRANCH Okayama Murata Mfg.Co..Ltd. Wakura Murata Mfg; Manuftr: MUR; Part_Type: *LF_C0805; TOLERANCE: 20%; VOLTAGE: 4V
C613 C615 C645 C646 = CAP_NP: CAP CHIP 4.7UF 6.3V(+-20%,X6S,0402); CLASS: DISCRETE; MATERIAL: X6S; Manuf_PN: GRM155C80J475M; Manuf_name: MURATA ERIE N.A. INC TAIWAN BRANCH Okayama Murata Mfg.Co.,; Manuftr: MUR; Part_Type: *LF_C0402; TOLERANCE: 20%; VOLTAGE: 6.3V
C616 C617 C647-C650 = CAP_NP: CAP CHIP 4.7UF 6.3V(+-20%,X6S,0402); CLASS: DISCRETE; MATERIAL: X6S; Manuf_PN: GRM155C80J475M; Manuf_name: MURATA ERIE N.A. INC TAIWAN BRANCH Okayama Murata Mfg.Co.,; Manuftr: MUR; Not_insert: NI; Part_Type: *LF_C0402; TOLERANCE: 20%; VOLTAGE: 6.3V
L7 = L: IND SMD 10UH.+-20%.155MA.(LB2518T100M); CLASS: DISCRETE; Current_Amp: 165MA; MATERIAL: IND; Manuf_PN: LB2518T100M; Manuf_name: TAIYO YUDEN CO..LTD; Manuftr: TAY; Part_Type: Inductor
R2910 = R: RES CHIP 0(1/20W,+-5%,0201); CLASS: DISCRETE; MATERIAL: CHIP; Manuf_PN: RC0201JR-130RL; Manuf_name: YAGEO CORPORATION; Manuftr: YGO; Part_Type: *LF_Resistor; TOLERANCE: 5%; WATTAGE: 1/20W
R3129-R3132 R3161 R3162 R3265 = R: RES CHIP 1K 1/16W +-1% (0402); CLASS: DISCRETE; MATERIAL: CHIP; Manuf_PN: RR0510S-102-FN; Manuf_name: CYNTEC CO.. LTD.; Manuftr: CYN; Part_Type: *LF_Resistor; TOLERANCE: 1%; WATTAGE: 1/16W
L8 = L: IND SMD 10UH 20% 3.7A(CMLE053T-100MS); CLASS: DISCRETE; Current_Amp: 3.7A; MATERIAL: IND; Manuf_PN: CMLE053T-100MS; Manuf_name: CYNTEC CO., LTD.; Manuftr: CYN; Part_Type: *LF_Inductor
R4308 R4309 R4311 = R: RES CHIP 0.001 1W +-1%(1206); CLASS: DISCRETE; MATERIAL: CHIP; Manuf_PN: LR1206-21R001F4; Manuf_name: RALEC ELECTRONIC CO.; Manuftr: RLC; Part_Type: *LF_Resistor; TOLERANCE: 1%; WATTAGE: 1W
C948 = CAP_NP: CAP CHIP 10U 25V(+-10%,X6S,0805,H1.25); CLASS: DISCRETE; MATERIAL: X6S; Manuf_PN: MAG05X6S1E106K; Manuf_name: Matsuki Precision Ceramic Co., Ltd.Matsuki Polymer Technology Co., Ltd.; Manuftr: MKP; Part_Type: *LF_C0805; TOLERANCE: 10%; VOLTAGE: 25V
C2 C949 C950 = CAP_NP: CAP CHIP 100NF 50V(+-10%,X7R,0402); CLASS: DISCRETE; MATERIAL: X7R; Manuf_PN: CC0402KRX7R9BB104; Manuf_name: YAGEO CORPORATION; Manuftr: YGO; Part_Type: *LF_C0402; TOLERANCE: 10%; VOLTAGE: 50V
C951 = CAP_NP: CAP CHIP 0.01U 50V(+-10%,X7R,0402); CLASS: DISCRETE; MATERIAL: X7R; Manuf_PN: WBM155R71H103K; Manuf_name: MURATA ERIE N.A. INC TAIWAN BRANCH Okayama Murata Mfg.Co.,Ltd.; Manuftr: MUR; Part_Type: *LF_C0402; TOLERANCE: 10%; VOLTAGE: 50V
J47 = SCONN8_5153000801V01: CONN SMD FPC 8P 1R FR(P0.5,H1.8); CLASS: IO; ESD_CDM: N/A; ESD_HBM: N/A; ESD_MM: N/A; MATERIAL: IO; MSD: NA; Manuf_PN: 51530-00801-V01; Manuf_name: ACES ELECTRONIC CO., LTD.; Manuftr: ACS; PIN_LENGTH_LONG_PIN: 0 MILS; PIN_LENGTH_SHORT_PIN: 0 MILS; Part_Type: *LF_Connector
R3123 R3124 = R: RES CHIP 100K 1/16W +-1% (0402); CLASS: DISCRETE; MATERIAL: CHIP; Manuf_PN: RR0510S-104-FN; Manuf_name: CYNTEC CO.. LTD.; Manuftr: CYN; Part_Type: *LF_Resistor; TOLERANCE: 1%; WATTAGE: 1/16W
R3125-R3128 = R: RES CHIP 1K 1/16W +-1% (0402); CLASS: DISCRETE; MATERIAL: CHIP; Manuf_PN: RR0510S-102-FN; Manuf_name: CYNTEC CO.. LTD.; Manuftr: CYN; Not_insert: NI; Part_Type: *LF_Resistor; TOLERANCE: 1%; WATTAGE: 1/16W
R3264 = R: RES CHIP 15K 1/16W +-1% (0402); CLASS: DISCRETE; MATERIAL: CHIP; Manuf_PN: WR04X1502FTL; Manuf_name: WALSIN TECHNOLOGY CORPORATION; Manuftr: WTC; Part_Type: *LF_Resistor; TOLERANCE: 1%; WATTAGE: 1/16W
R3266 R4258-R4261 = R: RES CHIP 33 1/16W +-5% (0402); CLASS: DISCRETE; MATERIAL: CHIP; Manuf_PN: RR0510S-330-JN; Manuf_name: CYNTEC CO.. LTD.; Manuftr: CYN; Part_Type: *LF_Resistor; TOLERANCE: 5%; WATTAGE: 1/16W
R3268 = R: RES CHIP 150 1/16W +-5%(0402); CLASS: DISCRETE; MATERIAL: CHIP; Manuf_PN: WR04X151 JTL; Manuf_name: WALSIN TECHNOLOGY CORPORATION; Manuftr: WTC; Part_Type: *LF_Resistor; TOLERANCE: 5%; WATTAGE: 1/16W
R3 R4 R3270 = R: RESISTOR CHIP 0 1/16W +-5%(0402); CLASS: DISCRETE; MATERIAL: CHIP; Manuf_PN: RR0510X-000-XN; Manuf_name: CYNTEC CO.. LTD.; Manuftr: CYN; Part_Type: *LF_Resistor; TOLERANCE: 5%; WATTAGE: 1/16W
R3271-R3273 R3284 = R: RES CHIP 4.75K 1/16W +-1%(0402); CLASS: DISCRETE; MATERIAL: CHIP; Manuf_PN: RR0510S-4751-FN; Manuf_name: CYNTEC CO.. LTD.; Manuftr: CYN; Part_Type: *LF_Resistor; TOLERANCE: 1%; WATTAGE: 1/16W
U56 = M24128BRMN6TP: IC EEPROM(8P)M24128-BRMN6TP(SO); CLASS: IC; MATERIAL: IC; Manuf_name: SGS-THOMSON(STMicroelectronics); Manuftr: SGT; Part_Type: *LF_Chipset
U58 = AT24C32: IC SOCKET SMD 8P 2R SPI(P1.27,H5.4); CLASS: IO; ESD_CDM: N/A; ESD_HBM: N/A; ESD_MM: N/A; MATERIAL: IO; MSD: NA; Manuf_PN: ACA-SPI-004-P09; Manuf_name: LOTES(CHIA TSE TERMINAL INDUSTRYLOTES SUZHOU CO.,; Manuftr: LTS; PIN_LENGTH_LONG_PIN: 0 MILS; PIN_LENGTH_SHORT_PIN: 0 MILS; Part_Type: *LF_Connector
C1 C1233 C1234 = CAP_NP: CAP CHIP 100NF 50V(+-10%,X7R,0402); CLASS: DISCRETE; MATERIAL: X7R; Manuf_PN: CC0402KRX7R9BB104; Manuf_name: YAGEO CORPORATION; Manufacturer: AVX; Manuftr: YGO; Part_Type: *LF_C0402; TOLERANCE: 10%; VOLTAGE: 50V
C1235 = CAP_NP: CAP CHIP 1UF 25V(+-10%,X6S,0402); CLASS: DISCRETE; MATERIAL: X6S; Manuf_PN: GRM155C81E105K; Manuf_name: MURATA ERIE N.A. INC TAIWAN BRANCH Okayama Murata Mfg.Co..Ltd.Wakura Murata Mfg.; Manuftr: MUR; Part_Type: *LF_C0402; TOLERANCE: 10%; VOLTAGE: 25V
R6 = Q_SP_RES4P: RES CHIP 0.002 2W +-1%(2512); CLASS: DISCRETE; EE_CHECK_LIST: R2512_4P.xls; MATERIAL: CHIP; Manuf_PN: WW25NR002FTL; Manuf_name: WALSIN TECHNOLOGY CORPORATION; Manuftr: WTC; Part_Type: *LF_Resistor; TOLERANCE: 1%; WATTAGE: 2W
R7 R8 = R: RES CHIP 10 1/16W +-1%(0402); CLASS: DISCRETE; MATERIAL: CHIP; Manuf_PN: RM04FTN10R0; Manuf_name: TA-I TECHNOLOGY CO..LTD.; Manuftr: TAI; Part_Type: *LF_Resistor; TOLERANCE: 1%; WATTAGE: 1/16W
R9 R10 R4363-R4368 R4374 R4375 = R: RES CHIP 22 1/16W +-1%(0402); BOM: AST2300; CLASS: DISCRETE; MATERIAL: CHIP; Manuf_PN: CR0222R0F002S; Manuf_name: RTECH TECHNOLOGY CO..LTD. (Compostar); Manufacturer: CYN; Manuftr: RHT; Part_Type: *LF_Resistor; TOLERANCE: 1%; WATTAGE: 1/16W
R3046 R4371-R4373 = R: RES CHIP 4.7K 1/16W +-5% (0402); CLASS: DISCRETE; MATERIAL: CHIP; Manuf_PN: RR0510S-472-JN; Manuf_name: CYNTEC CO.. LTD.; Manufacturer: CYN; Manuftr: CYN; Part_Type: *LF_Resistor; TOLERANCE: 5%; WATTAGE: 1/16W
R4034 = R: RES CHIP 22 1/16W +-1%(0402); CLASS: DISCRETE; MATERIAL: CHIP; Manuf_PN: CR0222R0F002S; Manuf_name: RTECH TECHNOLOGY CO..LTD. (Compostar); Manuftr: RHT; Part_Type: *LF_Resistor; TOLERANCE: 1%; WATTAGE: 1/16W
R4369 R4370 = R: RES CHIP 220 1/16W +-5%(0402); CLASS: DISCRETE; MATERIAL: CHIP; Manuf_PN: RR0510S-221-JN; Manuf_name: CYNTEC CO.. LTD.; Manuftr: CYN; Part_Type: *LF_Resistor; TOLERANCE: 5%; WATTAGE: 1/16W
R4376-R4381 = R: RES CHIP 1K 1/16W +-1% (0402); BOM: AST2300; CLASS: DISCRETE; FPLIST: R0402,R0402-0201; MATERIAL: CHIP; Manuf_PN: RR0510S-102-FN; Manuf_name: CYNTEC CO.. LTD.; Manufacturer: CYN; Manuftr: CYN; Part_Type: *LF_Resistor; TOLERANCE: 1%; WATTAGE: 1/16W
U2 = INA230AIRGTR: IC OTHER (16P) INA230AIRGTR (QFN 3X3); CLASS: IC; MATERIAL: IC; Manuf_name: TEXAS INSTRUMENTS SUPPLY CO.,; Manuftr: TIC; Part_Type: *LF_Chipset
U108 = PCA9846PW: IC OTHER(16P)PCA9846PW(TSSOP); CLASS: IC; MATERIAL: IC; Manuf_name: NXP semiconductors; Manuftr: NXP; Part_Type: *LF_Chipset
PC701 PC703 = CAP_NP: CAP CHIP 22U 6.3V(+-20%,X6S,0603)MUR; CLASS: DISCRETE; MATERIAL: X6S; Manuf_PN: GRM188C80J226M; Manuf_name: MURATA ERIE N.A. INC TAIWAN BRANCH Okayama Murata Mfg.Co.,Ltd.Wakura Murata Mfg. Co., Ltd.; Manufacturer: AVX; Manuftr: MUR; Part_Type: *LF_C0603; REUSE_ANNOTATE: TRUE; TOLERANCE: 20%; VOLTAGE: 6.3V
PC702 = CAP_NP: CAP CHIP 0.1U 25V(+-10%,X7R,0402); CLASS: DISCRETE; MATERIAL: X7R; Manuf_PN: CC0402KRX7R8BB104; Manuf_name: YAGEO CORPORATION; Manufacturer: MAT; Manuftr: YGO; Part_Type: *LF_C0402; REUSE_ANNOTATE: TRUE; SIDE: TOP; TOLERANCE: 10%; VOLTAGE: 25V
PC704 = CAP_NP: CAP CHIP 0.1U 25V(+-10%,X7R,0402); CLASS: DISCRETE; MATERIAL: X7R; Manuf_PN: CC0402KRX7R8BB104; Manuf_name: YAGEO CORPORATION; Manufacturer: AVX; Manuftr: YGO; Part_Type: *LF_C0402; REUSE_ANNOTATE: TRUE; SIDE: TOP; TOLERANCE: 10%; VOLTAGE: 25V
PL701 = L: EMI FILTER BLM18SN220TN1D(22,8000MA); CLASS: DISCRETE; Current_Amp: 8000MA; MATERIAL: IND; Manuf_name: MURATA ERIE N.A. INC TAIWAN BRANCH Okayama Murata Mfg.Co.,; Manuftr: MUR; Part_Type: *LF_Inductor; SIDE: TOP
PL702 = L: IND SMD 1UH 20% 4.2A(MLV-YT12N1R0M-C2Q); CLASS: DISCRETE; Current_Amp: 4.2A; MATERIAL: IND; Manuf_PN: MLV-YT12N1R0M-C2Q; Manuf_name: MAG. LAYERS (MAG.LAYERS Scientific-Technics Co.,; Manuftr: MAG; Part_Type: *LF_Inductor
PR701 = R: RES CHIP 10K 1/16W 5%(0402); CLASS: DISCRETE; MATERIAL: CHIP; Manuf_PN: RR0510S-103-JN; Manuf_name: CYNTEC CO.. LTD.; Manuftr: CYN; Part_Type: *LF_Resistor; TOLERANCE: 5%; WATTAGE: 1/16W
PU7 = MP1602GTF12Z: IC OTHER(6P)MP2152GTF-18-Z(SOT563); CLASS: IC; ESD_CDM: NA; ESD_HBM: NA; ESD_MM: NA; MATERIAL: IC; MSD: NA; Manuf_name: Monolithic Power Systems, Inc; Manuftr: MPS; PIN_LENGTH_LONG_PIN: 0 MILS; PIN_LENGTH_SHORT_PIN: 0 MILS; Part_Type: *LF_Chipset
H1 H2 H7-H30 = HOLE_N: CLASS: IO; DIP_SMD: DIP; MATERIAL: MECH; Part_Type: Mech
H3-H6 H31 = GND_HOLE: GNDHOLE_8PIN_C10D4B10; CLASS: IO; DIP_SMD: DIP; MATERIAL: MECH; Part_Type: Mech
H32-H36 = HOLE: CLASS: IO; DIP_SMD: DIP; MATERIAL: MECH; Part_Type: *LF_Mech
J9-J20 J51-J54 = PICOPROBE_B: Probe for DELTA-L measurement; CLASS: IO; DIP_SMD: DIP; MATERIAL: MISC; Part_Type: *LF_Misc
J24-J26 J50 = TDR_3P_TH2: TDR 3PIN,2X141MIL 1X100MIL P2P; CLASS: IO; MATERIAL: MISC; Part_Type: *LF_Misc
X1-X8 = TP_TDR_4P_FTS: DIFF_TEST_PAD DIP FOR FTS ONLY; CLASS: IO; DIP_SMD: DIP; MATERIAL: MISC; Part_Type: MISC
DM10 = DUMMY_SYMBOL: PM8535_FLASH; CLASS: IO; MATERIAL: MECH; Part_Type: Mech

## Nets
GND: C1.2 C537.2 C538.2 C539.2 C540.2 C541.2 C542.2 C543.2 C545.2 C546.2 C547.2 C548.2 C549.2 C550.2 C551.2 C552.2 C553.2 C554.2 C555.2 C556.2 C557.2 C558.2 C559.2 C560.2 C561.2 C562.2 C563.2 C564.2 C565.2 C566.2 C567.2 C568.2 C569.2 C570.2 C571.2 C572.2 C573.2 C574.2 C575.2 C576.2 C577.2 C578.2 C579.2 C580.2 C581.2 C582.2 C583.2 C584.2 C585.2 C586.2 C587.2 C588.2 C589.2 C590.2 C591.2 C592.2 C593.2 C594.2 C595.2 C596.2 C597.2 C598.2 C599.2 C600.2 C601.2 C602.2 C603.2 C604.2 C605.2 C606.2 C607.2 C609.2 C610.2 C611.2 C612.2 C613.2 C614.2 C615.2 C616.2 C617.2 C618.2 C619.2 C620.2 C621.2 C622.2 C623.2 C624.2 C625.2 C626.2 C627.2 C628.2 C629.2 C630.2 C631.2 C632.2 C633.2 C634.2 C635.2 C636.2 C637.2 C638.2 C639.2 C640.2 C641.2 C642.2 C643.2 C644.2 C645.2 C646.2 C647.2 C648.2 C649.2 C650.2 C651.2 C652.2 C653.2 C654.2 C655.2 C656.2 C657.2 C658.2 C659.2 C660.2 C661.2 C662.2 C663.2 C664.2 C665.2 C666.2 C948.2 C949.2 C950.2 C951.2 C1233.2 C1234.2 C1235.2 H3.2(GND2) H3.3(GND3) H3.4(GND4) H3.5(GND5) H3.6(GND6) H3.7(GND7) H3.8(GND8) H3.9(GND9) H4.2(GND2) H4.3(GND3) H4.4(GND4) H4.5(GND5) H4.6(GND6) H4.7(GND7) H4.8(GND8) H4.9(GND9) H5.2(GND2) H5.3(GND3) H5.4(GND4) H5.5(GND5) H5.6(GND6) H5.7(GND7) H5.8(GND8) H5.9(GND9) H6.2(GND2) H6.3(GND3) H6.4(GND4) H6.5(GND5) H6.6(GND6) H6.7(GND7) H6.8(GND8) H6.9(GND9) H31.2(GND2) H31.3(GND3) H31.4(GND4) H31.5(GND5) H31.6(GND6) H31.7(GND7) H31.8(GND8) H31.9(GND9) H32.1(GND) H33.1(GND) H34.1(GND) H35.1(GND) H36.1(GND) J47.8 J47.G1 J47.G2 PC701.2 PC702.2 PC703.2 PC704.2 PU7.1(GND) R3.2 R4.2 R2910.2 R3124.2 R3129.2 R3130.2 R3131.2 R3132.2 R3265.2 R4369.2 R4370.2 U2.10(GND) U2.TH U34.A2(VSS) U34.A3(VSS) U34.A4(VSS) U34.A5(VSS) U34.A6(VSS) U34.A7(VSS) U34.A16(VSS) U34.A25(VSS) U34.A34(VSS) U34.B3(VSS) U34.B6(VSS) U34.B7(VSS) U34.B16(VSS) U34.B25(VSS) U34.B34(VSS) U34.B35(VSS) U34.C4(VSS) U34.C7(VSS) U34.C9(VSS) U34.C11(VSS) U34.C13(VSS) U34.C15(VSS) U34.C16(VSS) U34.C18(VSS) U34.C20(VSS) U34.C22(VSS) U34.C24(VSS) U34.C25(VSS) U34.C27(VSS) U34.C29(VSS) U34.C31(VSS) U34.C33(VSS) U34.C34(VSS) U34.D3(VSS) U34.D6(VSS) U34.D7(VSS) U34.D8(VSS) U34.D10(VSS) U34.D12(VSS) U34.D14(VSS) U34.D16(VSS) U34.D17(VSS) U34.D19(VSS) U34.D21(VSS) U34.D23(VSS) U34.D25(VSS) U34.D26(VSS) U34.D28(VSS) U34.D30(VSS) U34.D32(VSS) U34.D34(VSS) U34.D35(VSS) U34.E4(VSS) U34.E7(VSS) U34.E16(VSS) U34.E25(VSS) U34.E34(VSS) U34.F3(VSS) U34.F6(VSS) U34.F9(VSS) U34.F11(VSS) U34.F13(VSS) U34.F15(VSS) U34.F18(VSS) U34.F20(VSS) U34.F22(VSS) U34.F24(VSS) U34.F27(VSS) U34.F29(VSS) U34.F31(VSS) U34.F34(VSS) U34.F35(VSS) U34.G4(VSS) U34.G15(VSS) U34.G34(VSS) U34.H3(VSS) U34.H6(VSS) U34.H8(VSS) U34.H9(VSS) U34.H10(VSS) U34.H11(VSS) U34.H12(VSS) U34.H13(VSS) U34.H14(VSS) U34.H15(VSS) U34.H16(VSS) U34.H17(VSS) U34.H18(VSS) U34.H19(VSS) U34.H21(VSS) U34.H22(VSS) U34.H23(VSS) U34.H24(VSS) U34.H26(VSS) U34.H34(VSS) U34.H35(VSS) U34.J4(VSS) U34.J8(VSS) U34.J9(VSS) U34.J10(VSS) U34.J11(VSS) U34.J12(VSS) U34.J13(VSS) U34.J14(VSS) U34.J15(VSS) U34.J16(VSS) U34.J17(VSS) U34.J18(VSS) U34.J19(VSS) U34.J21(VSS) U34.J22(VSS) U34.J23(VSS) U34.J24(VSS) U34.J26(VSS) U34.J34(VSS) U34.J35(VSS) U34.J36(VSS) U34.J37(VSS) U34.K1(VSS) U34.K2(VSS) U34.K3(VSS) U34.K4(VSS) U34.K5(VSS) U34.K6(VSS) U34.K8(VSS) U34.K9(VSS) U34.K10(VSS) U34.K11(VSS) U34.K12(VSS) U34.K13(VSS) U34.K14(VSS) U34.K15(VSS) U34.K16(VSS) U34.K17(VSS) U34.K18(VSS) U34.K19(VSS) U34.K20(VSS) U34.K21(VSS) U34.K22(VSS) U34.K23(VSS) U34.K24(VSS) U34.K25(VSS) U34.K29(VSS) U34.K32(VSS) U34.K34(VSS) U34.L3(VSS) U34.L6(VSS) U34.L8(VSS) U34.L9(VSS) U34.L10(VSS) U34.L11(VSS) U34.L12(VSS) U34.L14(VSS) U34.L15(VSS) U34.L16(VSS) U34.L17(VSS) U34.L18(VSS) U34.L19(VSS) U34.L21(VSS) U34.L23(VSS) U34.L24(VSS) U34.L25(VSS) U34.L35(VSS) U34.M4(VSS) U34.M8(VSS) U34.M9(VSS) U34.M10(VSS) U34.M11(VSS) U34.M12(VSS) U34.M14(VSS) U34.M16(VSS) U34.M18(VSS) U34.M20(VSS) U34.M22(VSS) U34.M24(VSS) U34.M34(VSS) U34.N3(VSS) U34.N6(VSS) U34.N8(VSS) U34.N9(VSS) U34.N10(VSS) U34.N11(VSS) U34.N12(VSS) U34.N13(VSS) U34.N15(VSS) U34.N17(VSS) U34.N19(VSS) U34.N21(VSS) U34.N23(VSS) U34.N25(VSS) U34.N29(VSS) U34.N35(VSS) U34.P4(VSS) U34.P7(VSS) U34.P9(VSS) U34.P11(VSS) U34.P12(VSS) U34.P14(VSS) U34.P16(VSS) U34.P18(VSS) U34.P20(VSS) U34.P22(VSS) U34.P24(VSS) U34.P26(VSS) U34.P31(VSS) U34.P34(VSS) U34.R3(VSS) U34.R6(VSS) U34.R8(VSS) U34.R10(VSS) U34.R12(VSS) U34.R13(VSS) U34.R15(VSS) U34.R17(VSS) U34.R19(VSS) U34.R21(VSS) U34.R23(VSS) U34.R25(VSS) U34.R35(VSS) U34.T4(VSS) U34.T7(VSS) U34.T9(VSS) U34.T11(VSS) U34.T12(VSS) U34.T14(VSS) U34.T16(VSS) U34.T18(VSS) U34.T20(VSS) U34.T22(VSS) U34.T24(VSS) U34.T26(VSS) U34.T29(VSS) U34.T34(VSS) U34.U3(VSS) U34.U6(VSS) U34.U8(VSS) U34.U10(VSS) U34.U12(VSS) U34.U13(VSS) U34.U15(VSS) U34.U17(VSS) U34.U19(VSS) U34.U21(VSS) U34.U23(VSS) U34.U25(VSS) U34.U35(VSS) U34.V4(VSS) U34.V7(VSS) U34.V9(VSS) U34.V11(VSS) U34.V12(VSS) U56.4(VSS) U58.4(GND) U108.8(VSS) ; also on sheet 12 13 17 18 19 20 21 22 23 24 25 26 27 28 29 30 31 32 33 34 35 36 37 38 39 40 41 42 43 44 45 46 47 48 49 50 52 53 54 55 56 57 66 67
P0V92: C537.1 C538.1 C539.1 C540.1 C541.1 C542.1 C543.1 C545.1 C546.1 C547.1 C548.1 C549.1 C550.1 C551.1 C552.1 C553.1 C554.1 C555.1 C556.1 C557.1 C558.1 C559.1 C560.1 C561.1 C562.1 C563.1 C564.1 C565.1 C566.1 C567.1 C568.1 C569.1 C570.1 C571.1 C572.1 C573.1 C574.1 C575.1 C576.1 C577.1 C578.1 C579.1 C580.1 C581.1 C582.1 C583.1 C584.1 C585.1 C586.1 C587.1 C588.1 C589.1 C590.1 C591.1 L8.1 R3161.1 R4308.2 R4309.2 R4311.2 U34.AA14(VDD_0V9) U34.AA16(VDD_0V9) U34.AA18(VDD_0V9) U34.AA20(VDD_0V9) U34.AA22(VDD_0V9) U34.AA24(VDD_0V9) U34.AB13(VDD_0V9) U34.AB15(VDD_0V9) U34.AB17(VDD_0V9) U34.AB19(VDD_0V9) U34.AB21(VDD_0V9) U34.AB23(VDD_0V9) U34.AB25(VDD_0V9) U34.AC14(VDD_0V9) U34.AC16(VDD_0V9) U34.AC18(VDD_0V9) U34.AC20(VDD_0V9) U34.AC22(VDD_0V9) U34.AC24(VDD_0V9) U34.AD13(VDD_0V9) U34.AD15(VDD_0V9) U34.AD17(VDD_0V9) U34.AD19(VDD_0V9) U34.AD21(VDD_0V9) U34.AD23(VDD_0V9) U34.AD25(VDD_0V9) U34.AE14(VDD_0V9) U34.AE16(VDD_0V9) U34.AE18(VDD_0V9) U34.AE20(VDD_0V9) U34.AE22(VDD_0V9) U34.AE24(VDD_0V9) U34.AE26(VDD_0V9) U34.AF15(VDD_0V9) U34.AF17(VDD_0V9) U34.AF19(VDD_0V9) U34.AF23(VDD_0V9) U34.AF25(VDD_0V9) U34.M15(VDD_0V9) U34.M17(VDD_0V9) U34.M19(VDD_0V9) U34.M23(VDD_0V9) U34.M25(VDD_0V9) U34.N14(VDD_0V9) U34.N16(VDD_0V9) U34.N18(VDD_0V9) U34.N20(VDD_0V9) U34.N22(VDD_0V9) U34.N24(VDD_0V9) U34.P13(VDD_0V9) U34.P15(VDD_0V9) U34.P17(VDD_0V9) U34.P19(VDD_0V9) U34.P21(VDD_0V9) U34.P23(VDD_0V9) U34.P25(VDD_0V9) U34.R14(VDD_0V9) U34.R16(VDD_0V9) U34.R18(VDD_0V9) U34.R20(VDD_0V9) U34.R22(VDD_0V9) U34.R24(VDD_0V9) U34.T13(VDD_0V9) U34.T15(VDD_0V9) U34.T17(VDD_0V9) U34.T19(VDD_0V9) U34.T21(VDD_0V9) U34.T23(VDD_0V9) U34.T25(VDD_0V9) U34.U14(VDD_0V9) U34.U16(VDD_0V9) U34.U18(VDD_0V9) U34.U20(VDD_0V9) U34.U22(VDD_0V9) U34.U24(VDD_0V9) U34.V13(VDD_0V9) U34.V15(VDD_0V9) U34.V17(VDD_0V9) U34.V19(VDD_0V9) U34.V21(VDD_0V9) U34.V23(VDD_0V9) U34.W14(VDD_0V9) U34.W16(VDD_0V9) U34.W18(VDD_0V9) U34.W20(VDD_0V9) U34.W22(VDD_0V9) U34.W24(VDD_0V9) U34.Y13(VDD_0V9) U34.Y15(VDD_0V9) U34.Y17(VDD_0V9) U34.Y19(VDD_0V9) U34.Y21(VDD_0V9) U34.Y23(VDD_0V9) U34.Y25(VDD_0V9) ; also on sheet 50 57
P1V8: C592.1 C593.1 C594.1 C595.1 C596.1 C597.1 C598.1 C599.1 C600.1 C601.1 C602.1 C603.1 C604.1 C605.1 C606.1 C607.1 C613.1 C615.1 C616.1 C617.1 C948.1 C949.1 C950.1 C951.1 L7.1 PC703.1 PC704.1 PL702.2 PU7.6(OUT) R3123.1 R3125.1 R3126.1 R3127.1 R3128.1 R3162.1 R3264.1 R3268.1 R3271.1 R3272.1 R3273.1 R3284.1 U34.AA26(VDDO_1V8) U34.AC34(VDDO_1V8) U34.AD28(VDDO_1V8) U34.AE34(VDDO_1V8) U34.AG31(VDDO_1V8) U34.AG34(VDDO_1V8) U34.AJ34(VDDO_1V8) U34.L31(VDDO_1V8) U34.L34(VDDO_1V8) U34.N34(VDDO_1V8) U34.P28(VDDO_1V8) U34.R26(VDDO_1V8) U34.R34(VDDO_1V8) U34.U26(VDDO_1V8) U34.U31(VDDO_1V8) U34.U34(VDDO_1V8) U56.8(VCC) U58.8(VCC) ; also on sheet 17 18 19 22 23 24 25 26 27 28 29 30 31 32 33 34 35 36 37 44 49 50 53 67
P1V8_EN: PU7.4(EN) ; also on sheet 12 44
P1V8_JTAG: J47.1 R3268.2
P3V3_STBY: C1.1 C1233.1 C1234.1 PL701.1 PR701.1 R3046.1 R4371.1 R4372.1 R4373.1 R4376.1 R4377.1 R4378.1 R4379.1 R4380.1 R4381.1 U2.9(VS) U108.1(VDD1) U108.16(VDD2) ; also on sheet 12 17 18 19 20 22 23 24 25 26 27 28 29 30 31 32 33 34 35 36 37 38 39 40 41 42 43 44 45 46 47 48 49 50 52 53 54 55 56 57 67
P12V_CONN: R6.2A U2.11(BUS) ; also on sheet 12 13
P12V_STBY: R6.1A ; also on sheet 42 50 56
VDDO_1V8: C609.1 C610.1 C611.1 C612.1 C614.1 L7.2 R3162.2 U34.AA31(VDDO_1V8_REF) U34.AA34(VDDO_1V8_REF) U34.N26(VDDA_DTM_ESD) U34.V28(VDDO_1V8_REF) U34.W26(VDDO_1V8_REF)
AVD_PCIE: C662.1 C663.1 C664.1 C665.1 C666.1 R4309.1 R4311.1 U34.AC26(AVD_PCIE) U34.AF13(AVD_PCIE) U34.AF21(AVD_PCIE) U34.M13(AVD_PCIE) U34.M21(AVD_PCIE) ; also on sheet 66
AVD_PCIE_Q: C651.1 C652.1 C653.1 C654.1 C655.1 C656.1 C657.1 C658.1 C659.1 C660.1 C661.1 L8.2 R3161.2 U34.AG13(AVD_PCIE_Q) U34.AG20(AVD_PCIE_Q) U34.L13(AVD_PCIE_Q) U34.L20(AVD_PCIE_Q) U34.V25(AVD_PCIE_Q)
AVD_PCIE_TX: C618.1 C619.1 C620.1 C621.1 C622.1 C623.1 C624.1 C625.1 C626.1 C627.1 C628.1 C629.1 C630.1 C631.1 C632.1 C633.1 C634.1 C635.1 C636.1 C637.1 C638.1 C639.1 C640.1 C641.1 C642.1 C643.1 C644.1 C645.1 C646.1 C647.1 C648.1 C649.1 C650.1 R4308.1 U34.AA7(AVD_PCIE_TX) U34.AA9(AVD_PCIE_TX) U34.AA11(AVD_PCIE_TX) U34.AB8(AVD_PCIE_TX) U34.AB10(AVD_PCIE_TX) U34.AC7(AVD_PCIE_TX) U34.AC9(AVD_PCIE_TX) U34.AC11(AVD_PCIE_TX) U34.AD8(AVD_PCIE_TX) U34.AD10(AVD_PCIE_TX) U34.P8(AVD_PCIE_TX) U34.P10(AVD_PCIE_TX) U34.R7(AVD_PCIE_TX) U34.R9(AVD_PCIE_TX) U34.R11(AVD_PCIE_TX) U34.T8(AVD_PCIE_TX) U34.T10(AVD_PCIE_TX) U34.U7(AVD_PCIE_TX) U34.U9(AVD_PCIE_TX) U34.U11(AVD_PCIE_TX) U34.V8(AVD_PCIE_TX) U34.V10(AVD_PCIE_TX) U34.W7(AVD_PCIE_TX) U34.W9(AVD_PCIE_TX) U34.W11(AVD_PCIE_TX) U34.Y8(AVD_PCIE_TX) U34.Y10(AVD_PCIE_TX)
DELTA_L_85_5IN_BOT_DN: J51.1 J52.2
DELTA_L_85_5IN_BOT_DP: J51.2 J52.1
DELTA_L_85_5IN_IN1_DN: J10.1 J13.2
DELTA_L_85_5IN_IN1_DP: J10.2 J13.1
DELTA_L_85_5IN_IN2_DN: J11.1 J14.2
DELTA_L_85_5IN_IN2_DP: J11.2 J14.1
DELTA_L_85_5IN_TOP_DN: J9.1 J12.2
DELTA_L_85_5IN_TOP_DP: J9.2 J12.1
DELTA_L_85_10IN_BOT_DN: J53.1 J54.2
DELTA_L_85_10IN_BOT_DP: J53.2 J54.1
DELTA_L_85_10IN_IN1_DN: J16.1 J19.2
DELTA_L_85_10IN_IN1_DP: J16.2 J19.1
DELTA_L_85_10IN_IN2_DN: J17.1 J20.2
DELTA_L_85_10IN_IN2_DP: J17.2 J20.1
DELTA_L_85_10IN_TOP_DN: J15.1 J18.2
DELTA_L_85_10IN_TOP_DP: J15.2 J18.1
JTAG_PESE_TDI_R: J47.3 R3270.2 R3271.2
JTAG_PESW_RSTB: J47.7 R3284.2 ; also on sheet 17
JTAG_PESW_TCK: J47.6 R3273.2 ; also on sheet 17
JTAG_PESW_TDI: R3270.1 ; also on sheet 17
JTAG_PESW_TDO: R3264.2 R3266.1 ; also on sheet 17
JTAG_PESW_TDO_R: J47.4 R3266.2
JTAG_PESW_TMS: J47.5 R3272.2 ; also on sheet 17
JTAG_PESW_TRSTB: J47.2 R3265.1 ; also on sheet 17
PD_EEPROM_A0: R3128.2 R3132.1 U56.1(E0)
PD_EEPROM_A1: R3127.2 R3131.1 U56.2(E1)
PD_EEPROM_A2: R3126.2 R3130.1 U56.3(E2)
PD_EEPROM_WC_N: R3125.2 R3129.1 U56.7(WC_N)
PD_I2C_MUX7_A0: R4369.1 U108.2(A0)
PD_I2C_MUX7_A1: R4370.1 U108.13(A1)
PD_INA230_A0: R3.1 U2.2(A0)
PD_INA230_A1: R4.1 U2.1(A1)
PD_PESW_VSS_J28: R2910.1 U34.J28(VSS)
PU_I2C_MUX7_SC3: R4372.2 U108.12(SC3)
PU_I2C_MUX7_SD3: R4373.2 U108.11(SD3)
PWRGD_P1V8: PR701.2 PU7.5(PG) ; also on sheet 19 23 38
RST_I2C_MUX7_N: C1235.1 R4371.2 U108.3(RESET#) ; also on sheet 47
SMB_BIC_CPLD_0_CLK: R4363.2 ; also on sheet 52
SMB_BIC_CPLD_0_CLK_R2: R4363.1 R4376.2 U108.5(SC0)
SMB_BIC_CPLD_0_DAT: R4364.2 ; also on sheet 52
SMB_BIC_CPLD_0_DAT_R2: R4364.1 R4377.2 U108.4(SD0)
SMB_BIC_CPLD_1_CLK: R4365.2 ; also on sheet 52
SMB_BIC_CPLD_1_CLK_R2: R4365.1 R4378.2 U108.7(SC1)
SMB_BIC_CPLD_1_DAT: R4366.2 ; also on sheet 52
SMB_BIC_CPLD_1_DAT_R2: R4366.1 R4379.2 U108.6(SD1)
SMB_BIC_VR_CLK: R4367.1 ; also on sheet 46
SMB_BIC_VR_CLK_R1: R4367.2 U108.14(SCL)
SMB_BIC_VR_DAT: R4368.1 ; also on sheet 46
SMB_BIC_VR_DAT_R1: R4368.2 U108.15(SDA)
SMB_INA230_ALERT_N: R4034.2 ; also on sheet 46
SMB_INA230_ALERT_N_R: R3046.2 R4034.1 U2.3(ALERT)
SMB_MUX_VR_CLK: R4374.2 ; also on sheet 56 57
SMB_MUX_VR_CLK_R: R4374.1 R4380.2 U108.10(SC2)
SMB_MUX_VR_DAT: R4375.2 ; also on sheet 56 57
SMB_MUX_VR_DAT_R: R4375.1 R4381.2 U108.9(SD2)
SMB_SENSOR_3V3SB_CLK_R1: R9.2 ; also on sheet 19 43 45 46
SMB_SENSOR_3V3SB_DAT_R1: R10.2 ; also on sheet 19 43 45 46
SMB_SENSOR_INA230_CLK_R1: R9.1 U2.5(SCL)
SMB_SENSOR_INA230_DAT_R1: R10.1 U2.4(SDA)
SPI_PESW_FLASH_CLK: R3124.1 U58.6(SCL) ; also on sheet 17
SPI_PESW_FLASH_CSB_0: R3123.2 U58.1(A0) ; also on sheet 17
SPI_PESW_FLASH_DAT_0: R4259.2 ; also on sheet 17
SPI_PESW_FLASH_DAT_0_R2: R4259.1 U58.5(SDA)
SPI_PESW_FLASH_DAT_1: R4260.1 ; also on sheet 17
SPI_PESW_FLASH_DAT_1_R2: R4260.2 U58.2(A1)
SPI_PESW_FLASH_DAT_2: R4261.1 ; also on sheet 17
SPI_PESW_FLASH_DAT_2_R2: R4261.2 U58.3(A2)
SPI_PESW_FLASH_DAT_3: R4258.2 ; also on sheet 17
SPI_PESW_FLASH_DAT_3_R2: R4258.1 U58.7(WP)
SW_P1V8: PL702.1 PU7.2(SW)
SW_P1V8_FLT: PC701.1 PC702.1 PL701.2 PU7.3(VIN)
TDR_DIFF_85_BOT_DN: X5.4(S2) X6.1(S1)
TDR_DIFF_85_BOT_DP: X5.1(S1) X6.4(S2)
TDR_DIFF_85_IN1_DN: X3.4(S2) X4.1(S1)
TDR_DIFF_85_IN1_DP: X3.1(S1) X4.4(S2)
TDR_DIFF_85_IN2_DN: X7.4(S2) X8.1(S1)
TDR_DIFF_85_IN2_DP: X7.1(S1) X8.4(S2)
TDR_DIFF_85_TOP_DN: X1.4(S2) X2.1(S1)
TDR_DIFF_85_TOP_DP: X1.1(S1) X2.4(S2)
TDR_GND: J24.1(GND) J25.1(GND) J26.1(GND) J50.1(GND) X1.2(P1) X1.3(P2) X2.2(P1) X2.3(P2) X3.2(P1) X3.3(P2) X4.2(P1) X4.3(P2) X5.2(P1) X5.3(P2) X6.2(P1) X6.3(P2) X7.2(P1) X7.3(P2) X8.2(P1) X8.3(P2)
TDR_SE_50_OHM_BOT: J50.2(IO1) J50.3(IO2)
TDR_SE_50_OHM_IN1: J25.2(IO1) J25.3(IO2)
TDR_SE_50_OHM_IN2: J26.2(IO1) J26.3(IO2)
TDR_SE_50_OHM_TOP: J24.2(IO1) J24.3(IO2)
TGND: J9.3 J10.3 J11.3 J12.3 J13.3 J14.3 J15.3 J16.3 J17.3 J18.3 J19.3 J20.3 J51.3 J52.3 J53.3 J54.3
TWI_PESW_EEPROM_CLK_0: U56.6(SCL) ; also on sheet 17
TWI_PESW_EEPROM_DAT_0: U56.5(SDA) ; also on sheet 17
VSENSE_P12V_INA230_INN: C2.2 R8.2 U2.12(IN-)
VSENSE_P12V_INA230_INP: C2.1 R7.2 U2.13(IN+)
VSENSE_P12V_INA230_R_INN: R6.1B R8.1
VSENSE_P12V_INA230_R_INP: R6.2B R7.1

Not connected (* = marked no-connect by the designer): DM10 1; H1 1(GND); H2 1(GND); H7 1(GND); H8 1(GND); H9 1(GND); H10 1(GND); H11 1(GND); H12 1(GND); H13 1(GND); H14 1(GND); H15 1(GND); H16 1(GND); H17 1(GND); H18 1(GND); H19 1(GND); H20 1(GND); H21 1(GND); H22 1(GND); H23 1(GND); H24 1(GND); H25 1(GND); H26 1(GND); H27 1(GND); H28 1(GND); H29 1(GND); H30 1(GND); U2 6(NC0)* 7(NC1)* 8(NC2)* 14(NC3)* 15(NC4)* 16(NC5)*; U34 J27(NC) K26(NC)

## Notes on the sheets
sheet 58
- Design specification
  P1V8
  Output Voltage = 1.8V∮5%
  Output Ripple & Noise <180mVpp
  Transient Tolerance = 180mV
  Max current = 1.68A
  Over-Current Protection(IC Rating) = 4A
  Current Step = 1.0A
  Slew Rate = 2.5A/us
  Work Frequency = 1100kHz
  Efficiency > 85% @TDC
- Vth=1.2V
- Fix Vout = 1.8V
- Note:
  Add PWRGD_P1V8 off page.
- Note:
  Add P1V8_EN offpage
- P1V8
sheet 59
- TDR
- TDR
sheet 60
- DUMMY SYMBOL
  PCIE SWITCH SPI FLASH
- DUMMY SYMBOL
sheet 61
- SMBus (8-bit) Address:0x80
- SMBus (8-Bit) Address:0xE2
- I2C MUX 7 (PCIe Switch / CPLD)
- INA230 / I2C MUX 7
sheet 62
- Note:
  SPI Flash is W25Q128FWSIQ.
- SPI flash socket
- JTAG
- Serial EEPROM 128kb
- TWI Address: 0xA0
- SPI FLASH / EEPROM / JTAG
sheet 63
- Hole
- CAD Note:
  H31 change to ground hole.
- Heat Sink Hole X2
- Ground Hole X4
- SMT NUT Hole: D2-7X5
- Top Side X6
- X12
- Bottom Side X6
- DELTA-L
- 5  INCH
- 10  INCH
- Mechanical/Delta-L
sheet 64
- Power Cap
- Note:
  AVD_PCIE Power cap will show on page 20.
- BOM Note:
  U34 change to PM8545B-FEI
- 0.1UF-Insert:13/Not Insert:25
  4.7UF-Insert:2/Not Insert:2
  10UF-0
  100UF-Insert:1
- GPV2  AVD_PCIE_Q/PCIE_TX
- 0.1UF-Insert:13/Not Insert:1
  4.7UF-Insert:2
  10UF-0
  100UF-Insert:1
- SPEC  AVD_PCIE_Q/PCIE_TX
- Layout Note:
  Place 0.1 uF cpas close to AVD_PCIE_TX pins
- Layout Note:
  Place 0.1 uF cpas close to AVD_PCIE_Q pins
- Layout Note:
  Place 0.1 uF cpas close to AVD_PCIE pins
- PCIE SWITCH (PWR2/VSS2)
sheet 65
- Power Cap
- Power Cap
- BOM Note:
  U34 change to PM8545B-FEI
- 0.1UF-Insert:18/Not Insert:24
  4.7UF-0
  10UF-Insert 6/Not Insert:1
  100UF- Insert:2/Not Insert:3
- GPV2  VDD_0V9
- 0.1UF-Insert:18/Not Insert:18
  4.7UF-0
  10UF-Insert:6
  100UF-Insert:2
- SPEC  VDD_0V9
- 0.1UF-Insert:14/Not Insert:6
  4.7UF-Insert:2/Not Insert:2
  10UF-0
  100UF- Insert:1
- GPV2  VDDO_1V8/1V8_REF
- 0.1UF-Insert:14
  4.7UF-Insert:2
  10UF-0
  100UF-Insert:1
- SPEC  VDDO_1V8/1V8_REF
- Layout Note:
  Place 0.1 uF cpas close to VDD_0V9 pins
- Layout Note:
  Place 0.1 uF cpas close to VDD_1V8 pins
- Layout Note:
  Place 0.1 uF cpas close to VDD_1V8_REF pins
- PCIE SWITCH (PWR1/VSS1)
